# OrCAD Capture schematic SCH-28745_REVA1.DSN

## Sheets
1 TITLE PAGE: title: FRDM-KW019032; rev: A1; company: Freescale Semiconductor; note: SCH-28745 PDF: SPF-28745; note: 6501 William Cannon Drive West; note: Austin, TX 78735-8598
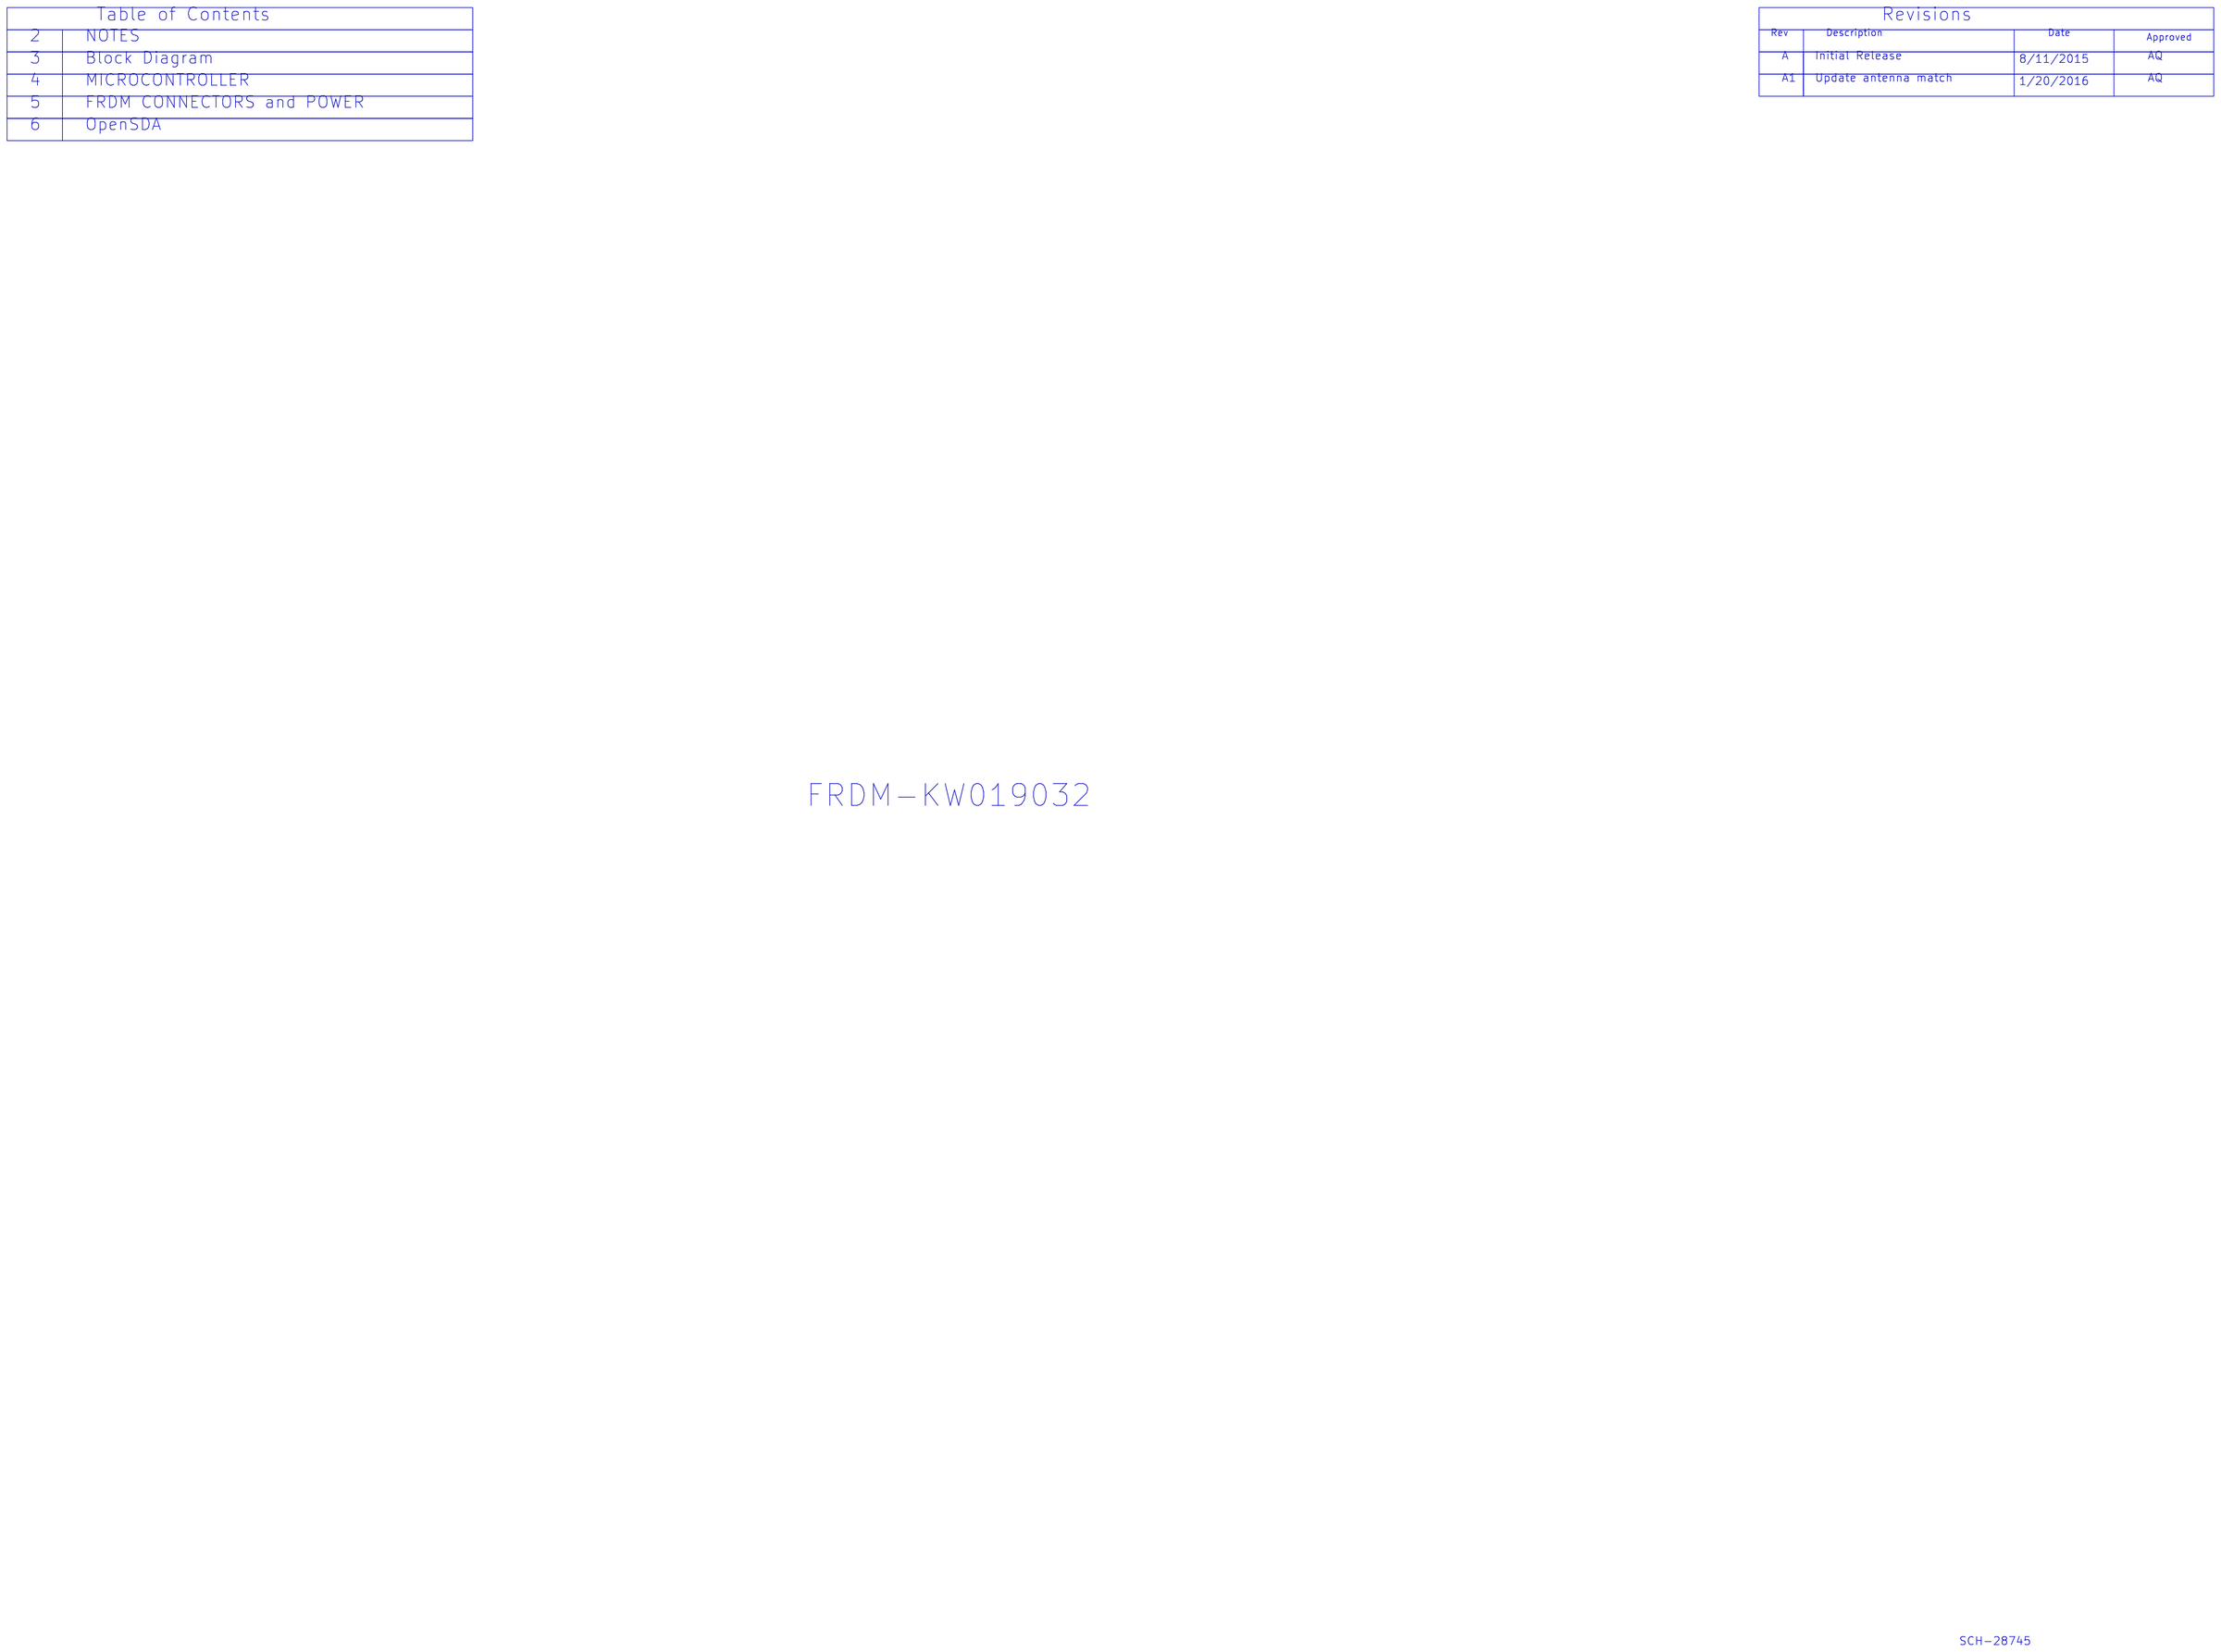
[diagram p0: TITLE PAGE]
2 NOTES
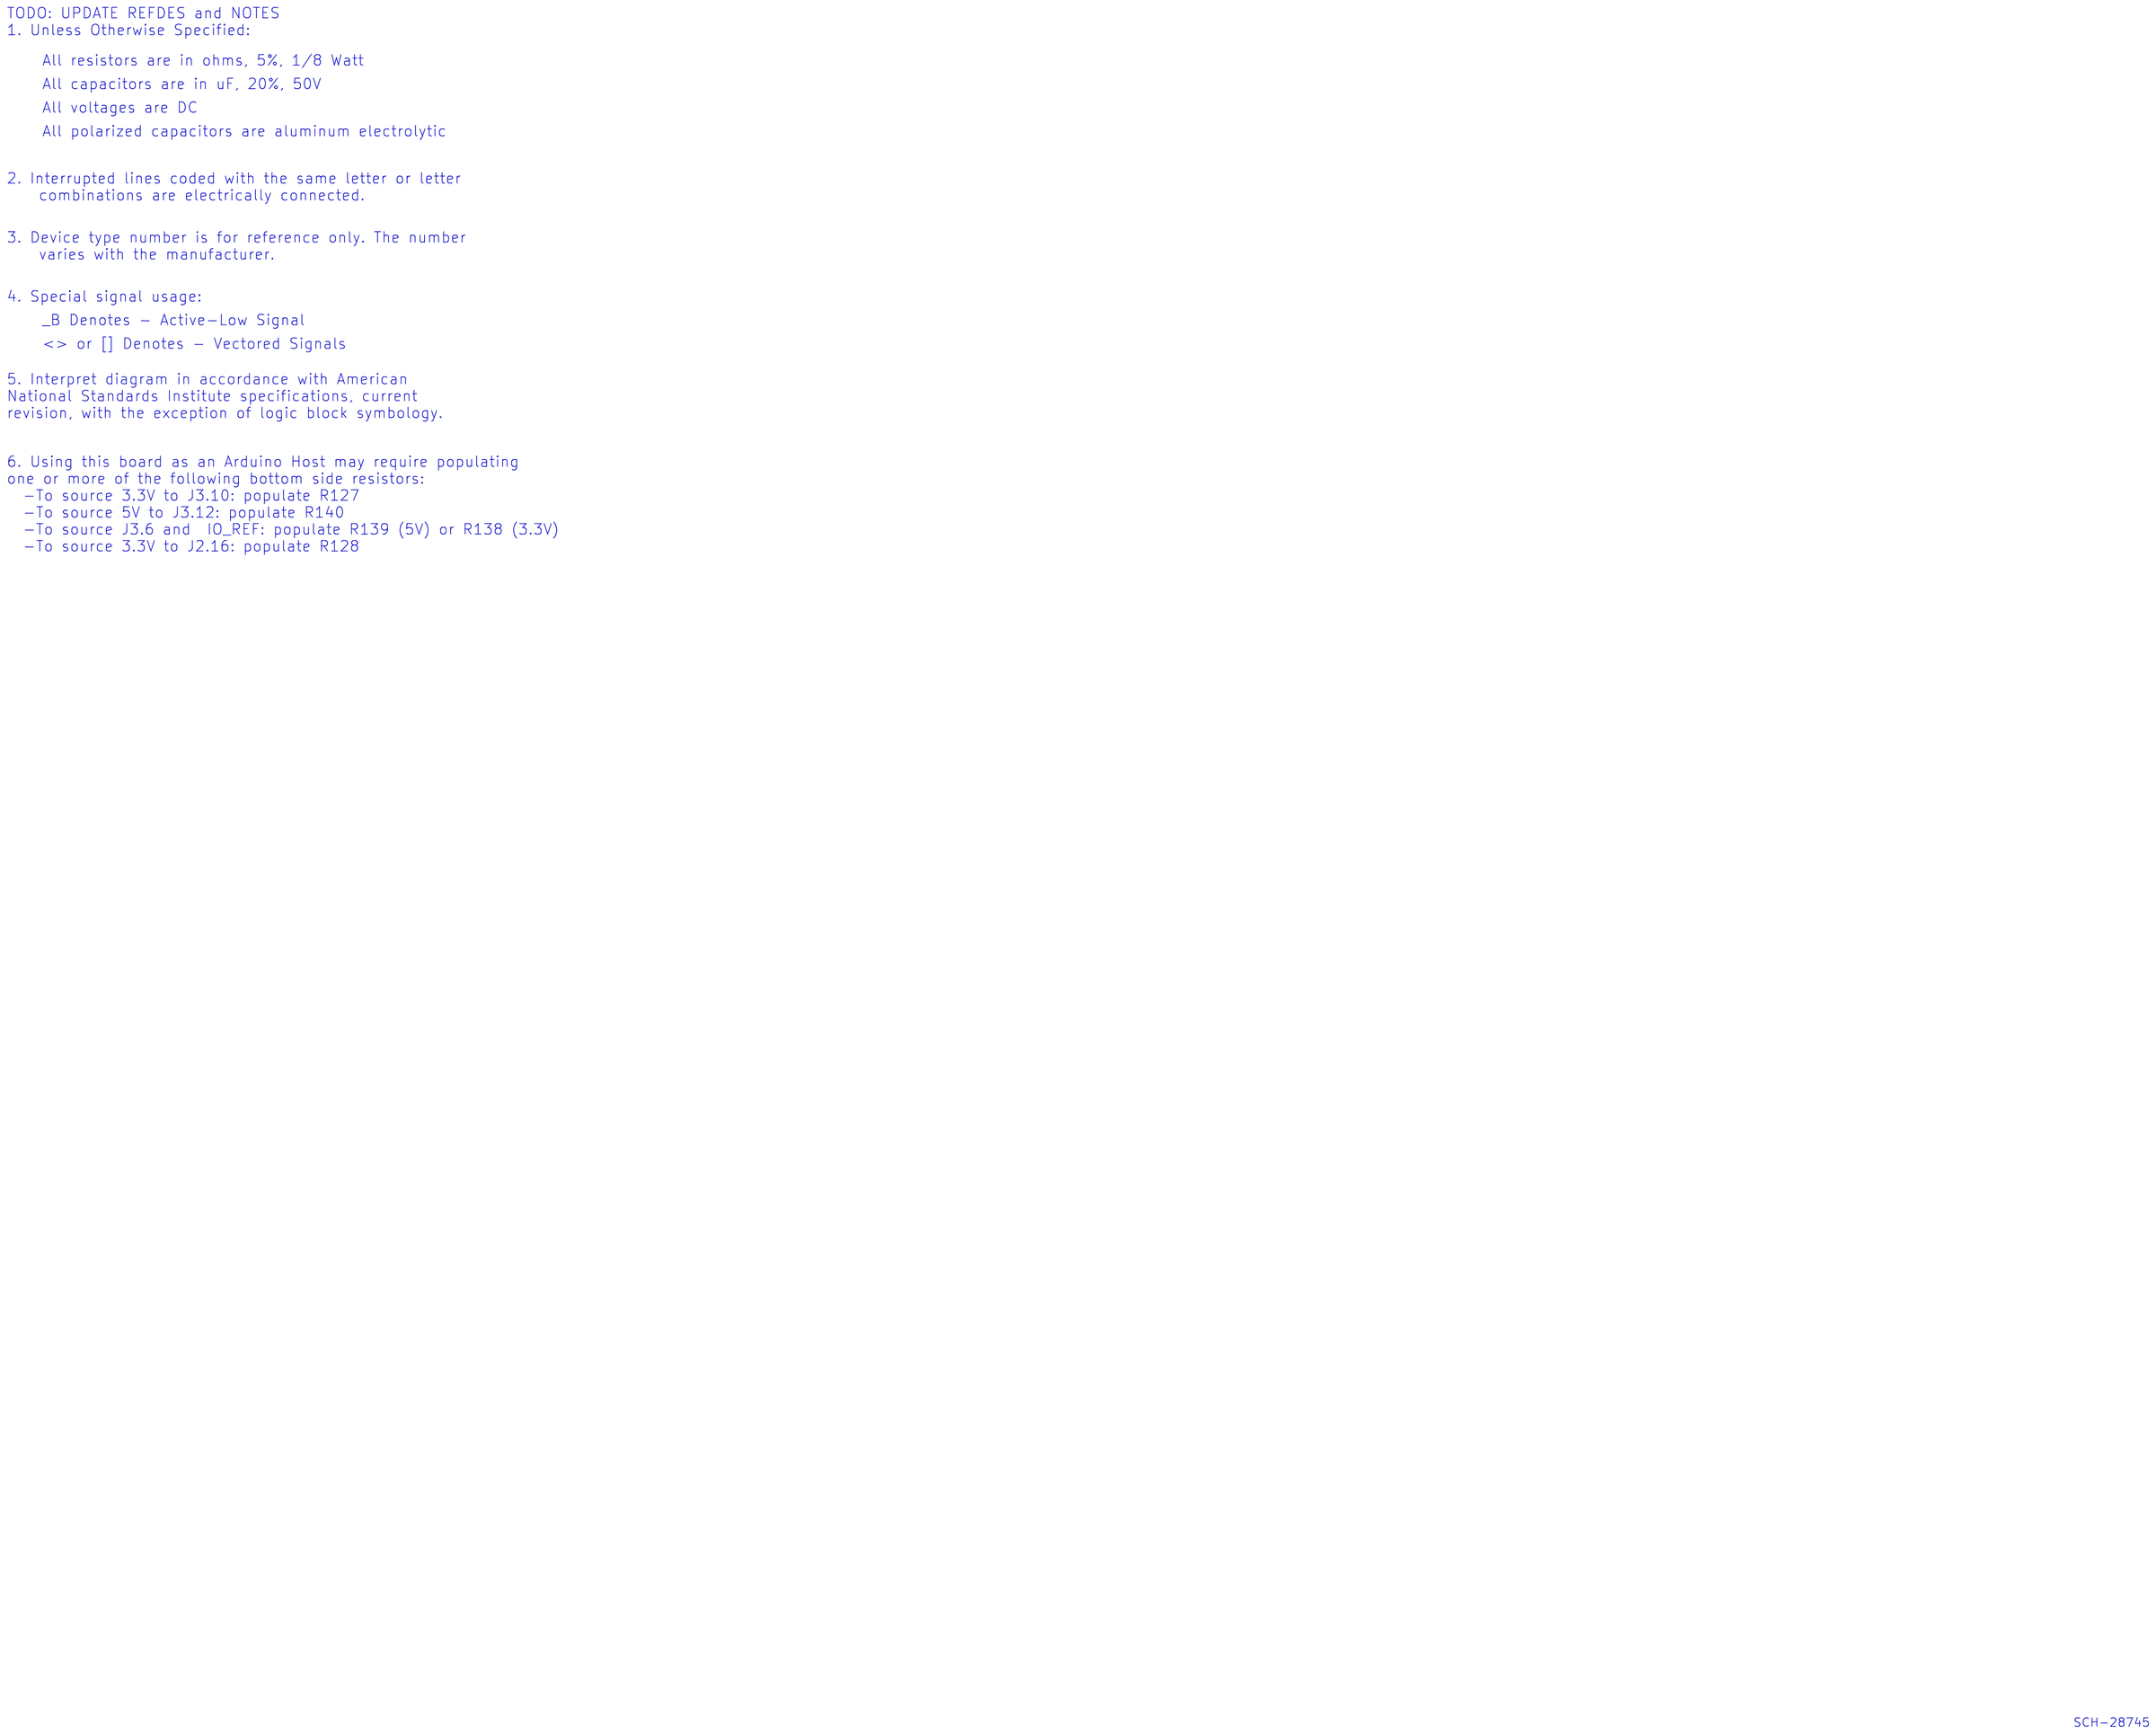
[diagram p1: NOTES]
3 BLOCK DIAGRAM
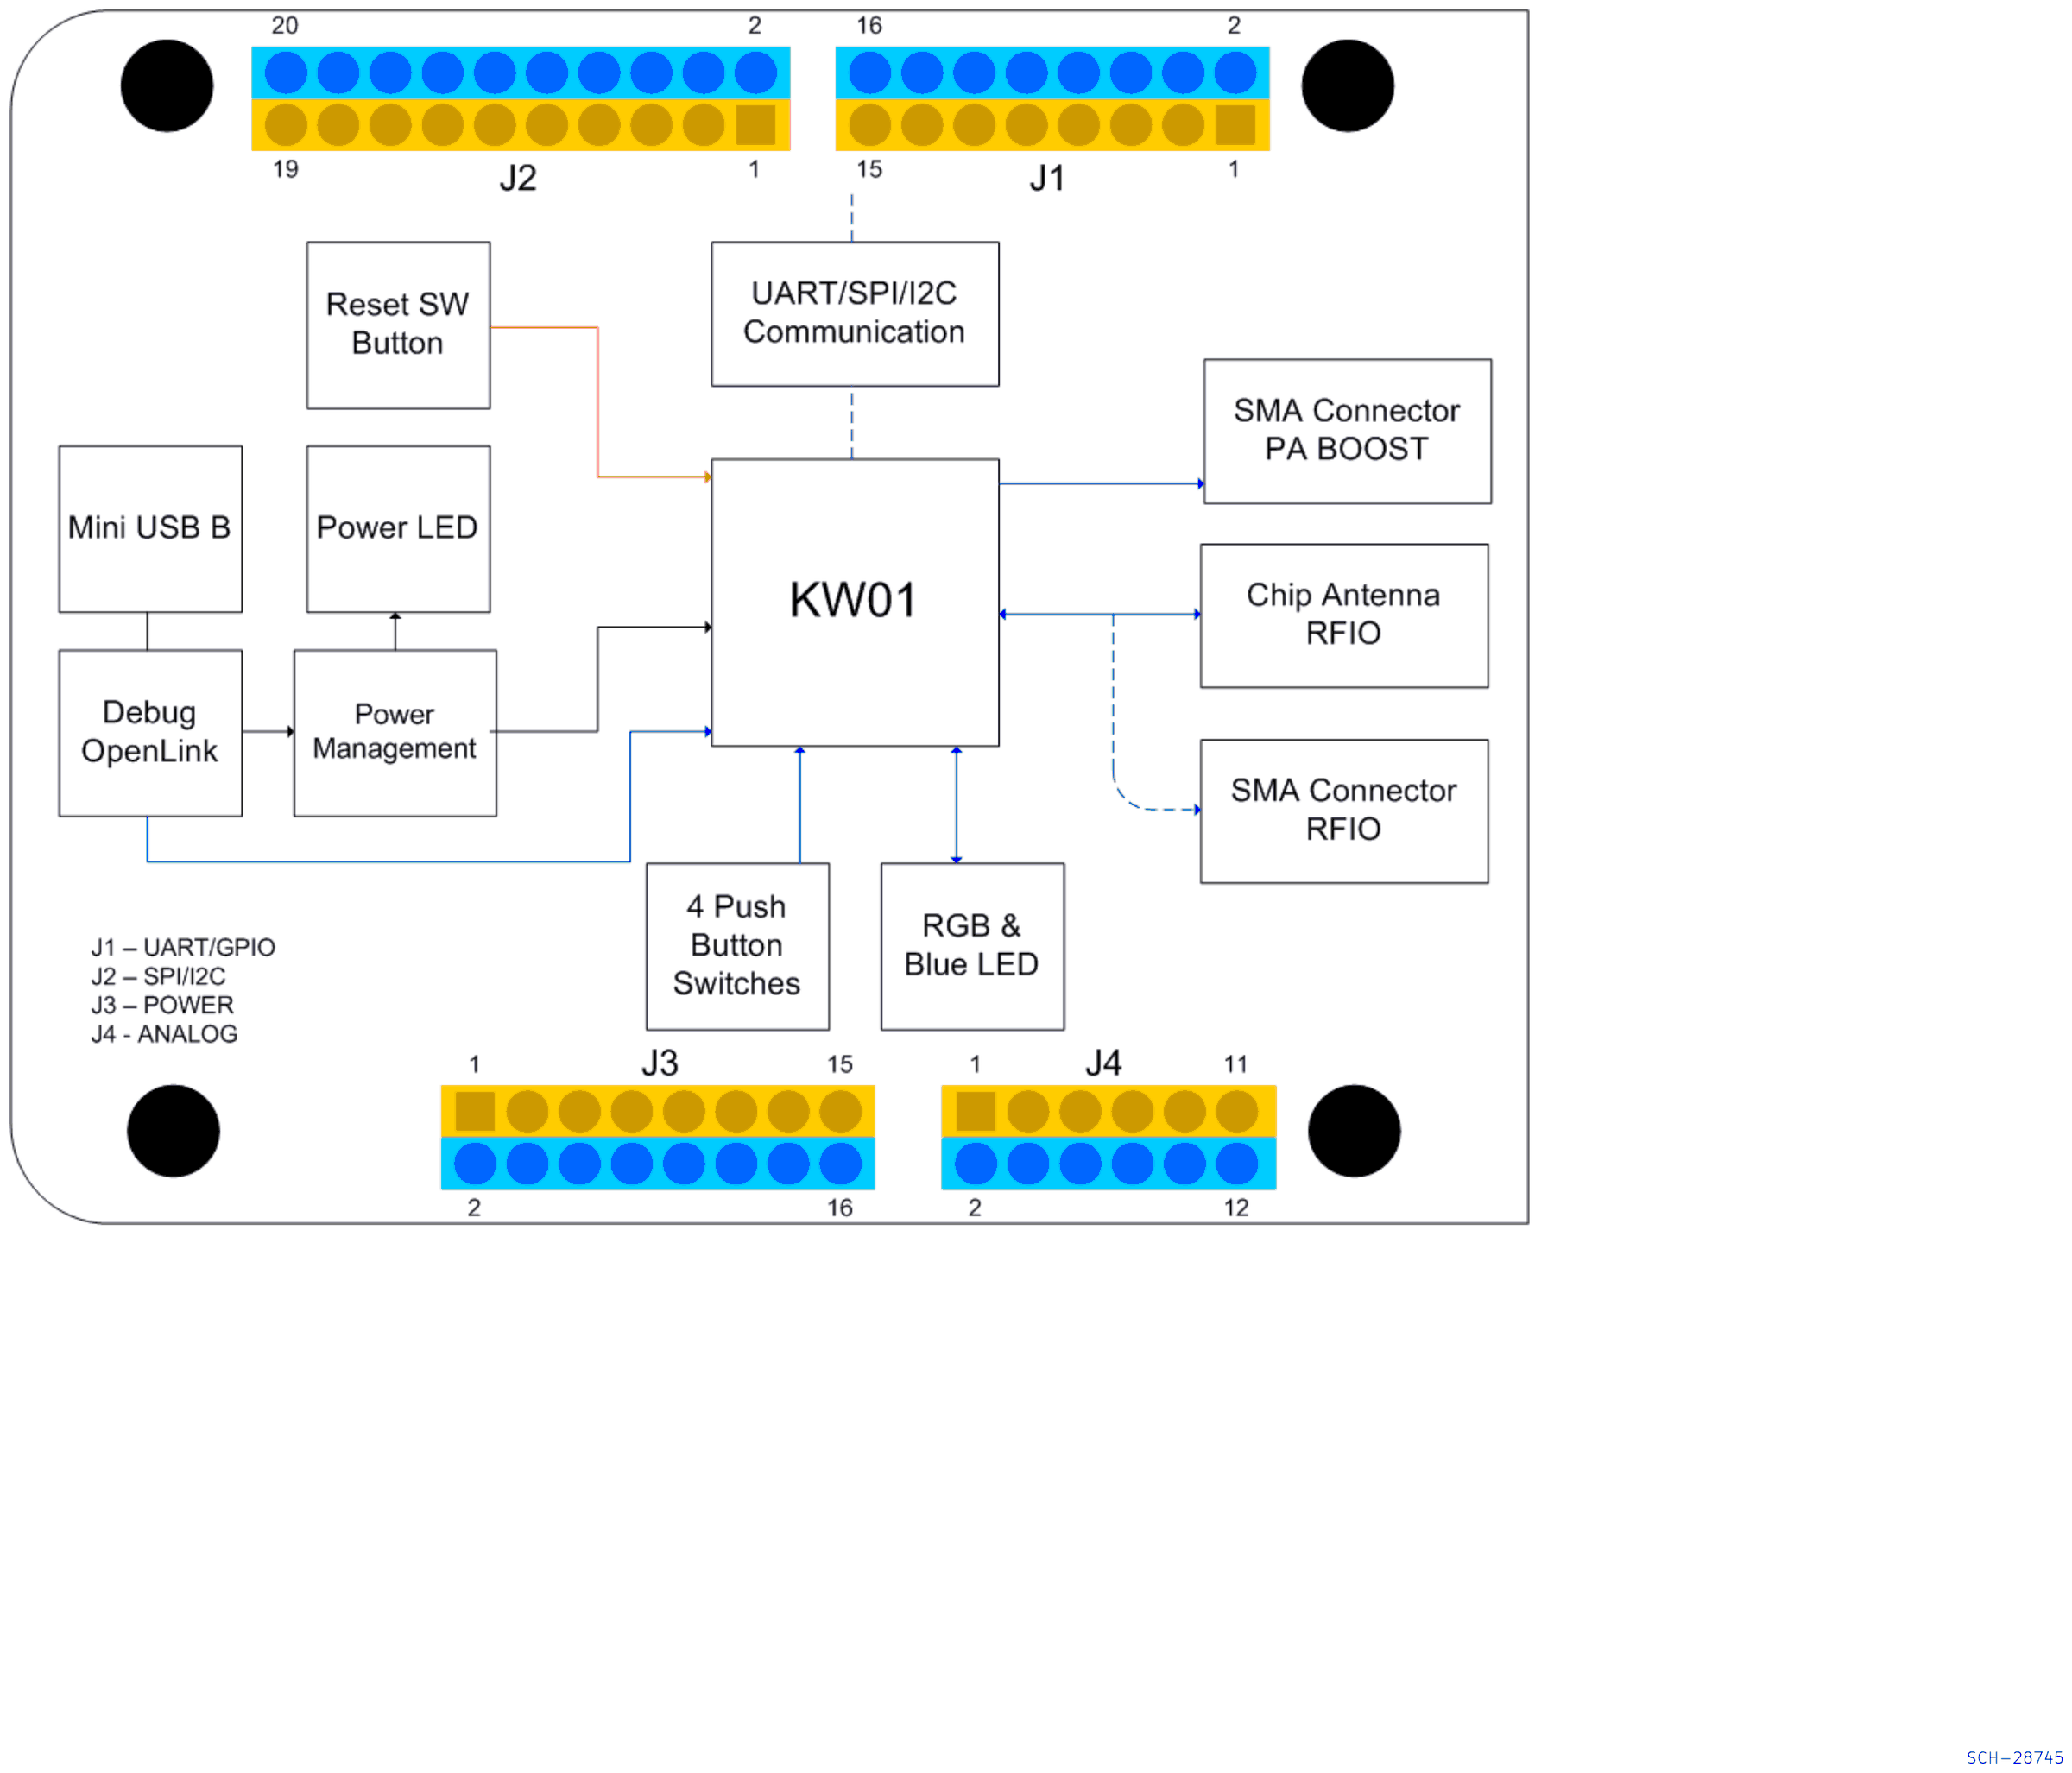
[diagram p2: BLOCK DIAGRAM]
4 MICROCONTROLLER: size C
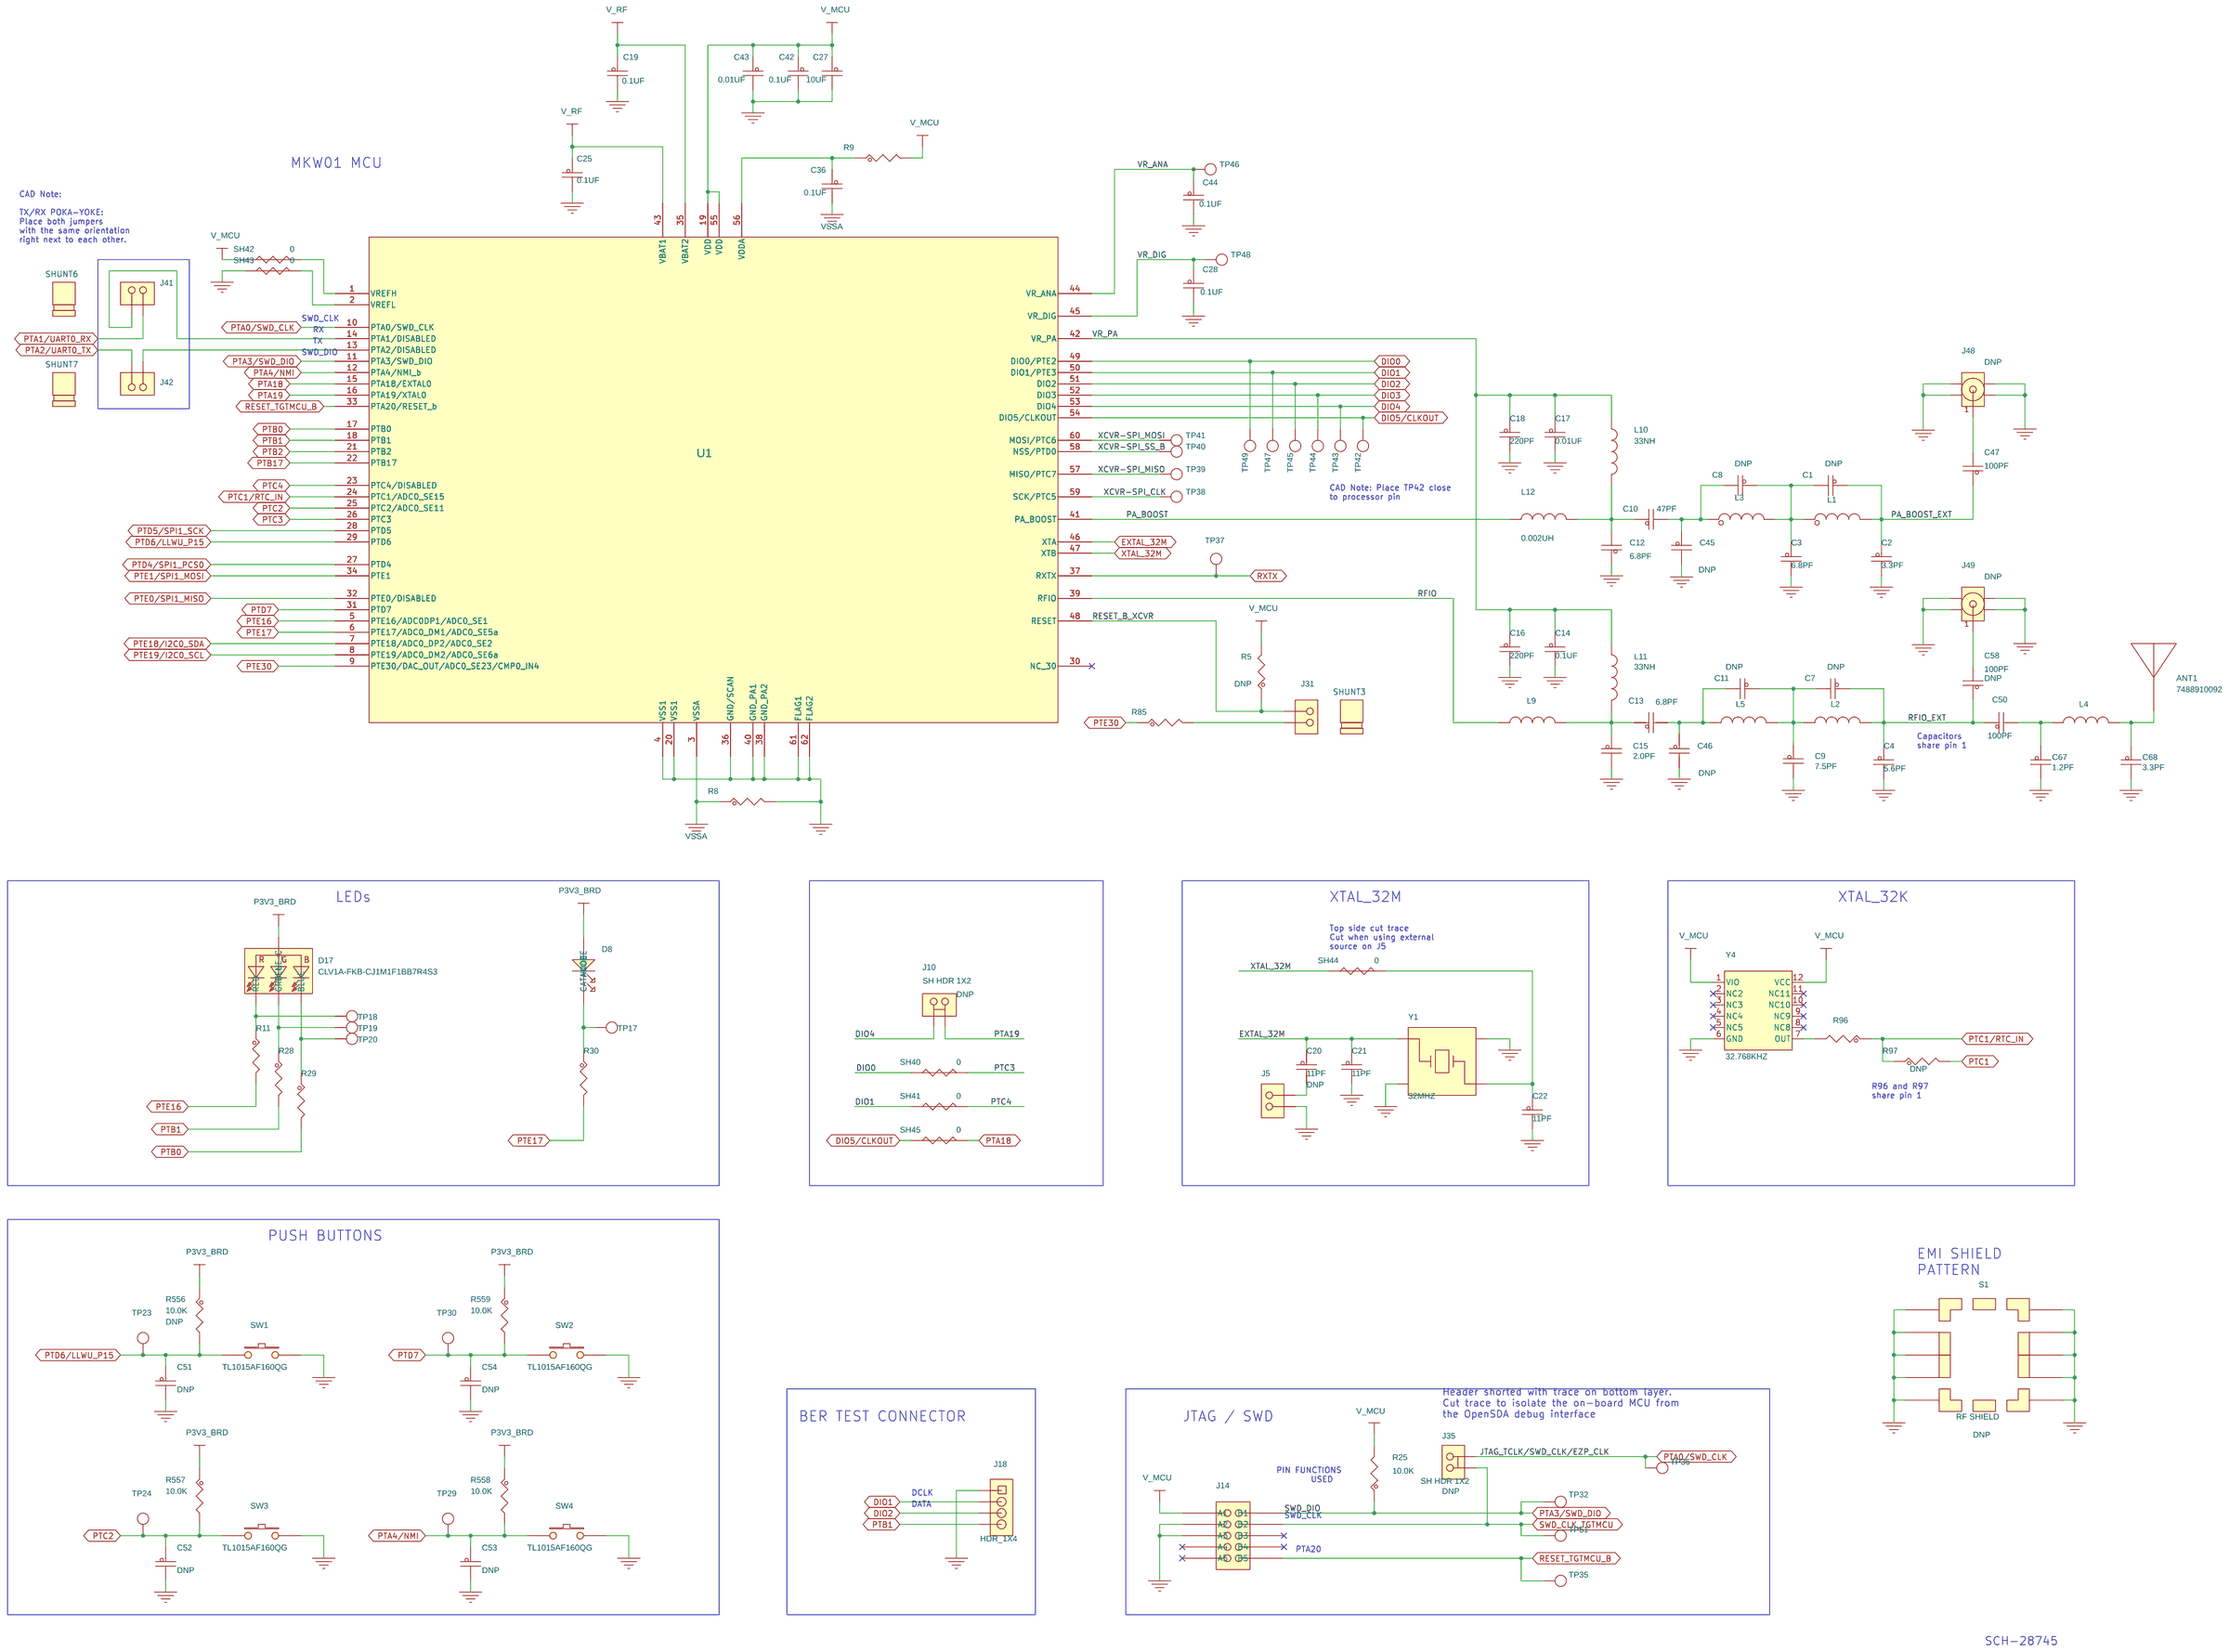
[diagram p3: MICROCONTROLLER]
5 POWER AND CONNECTORS: size C
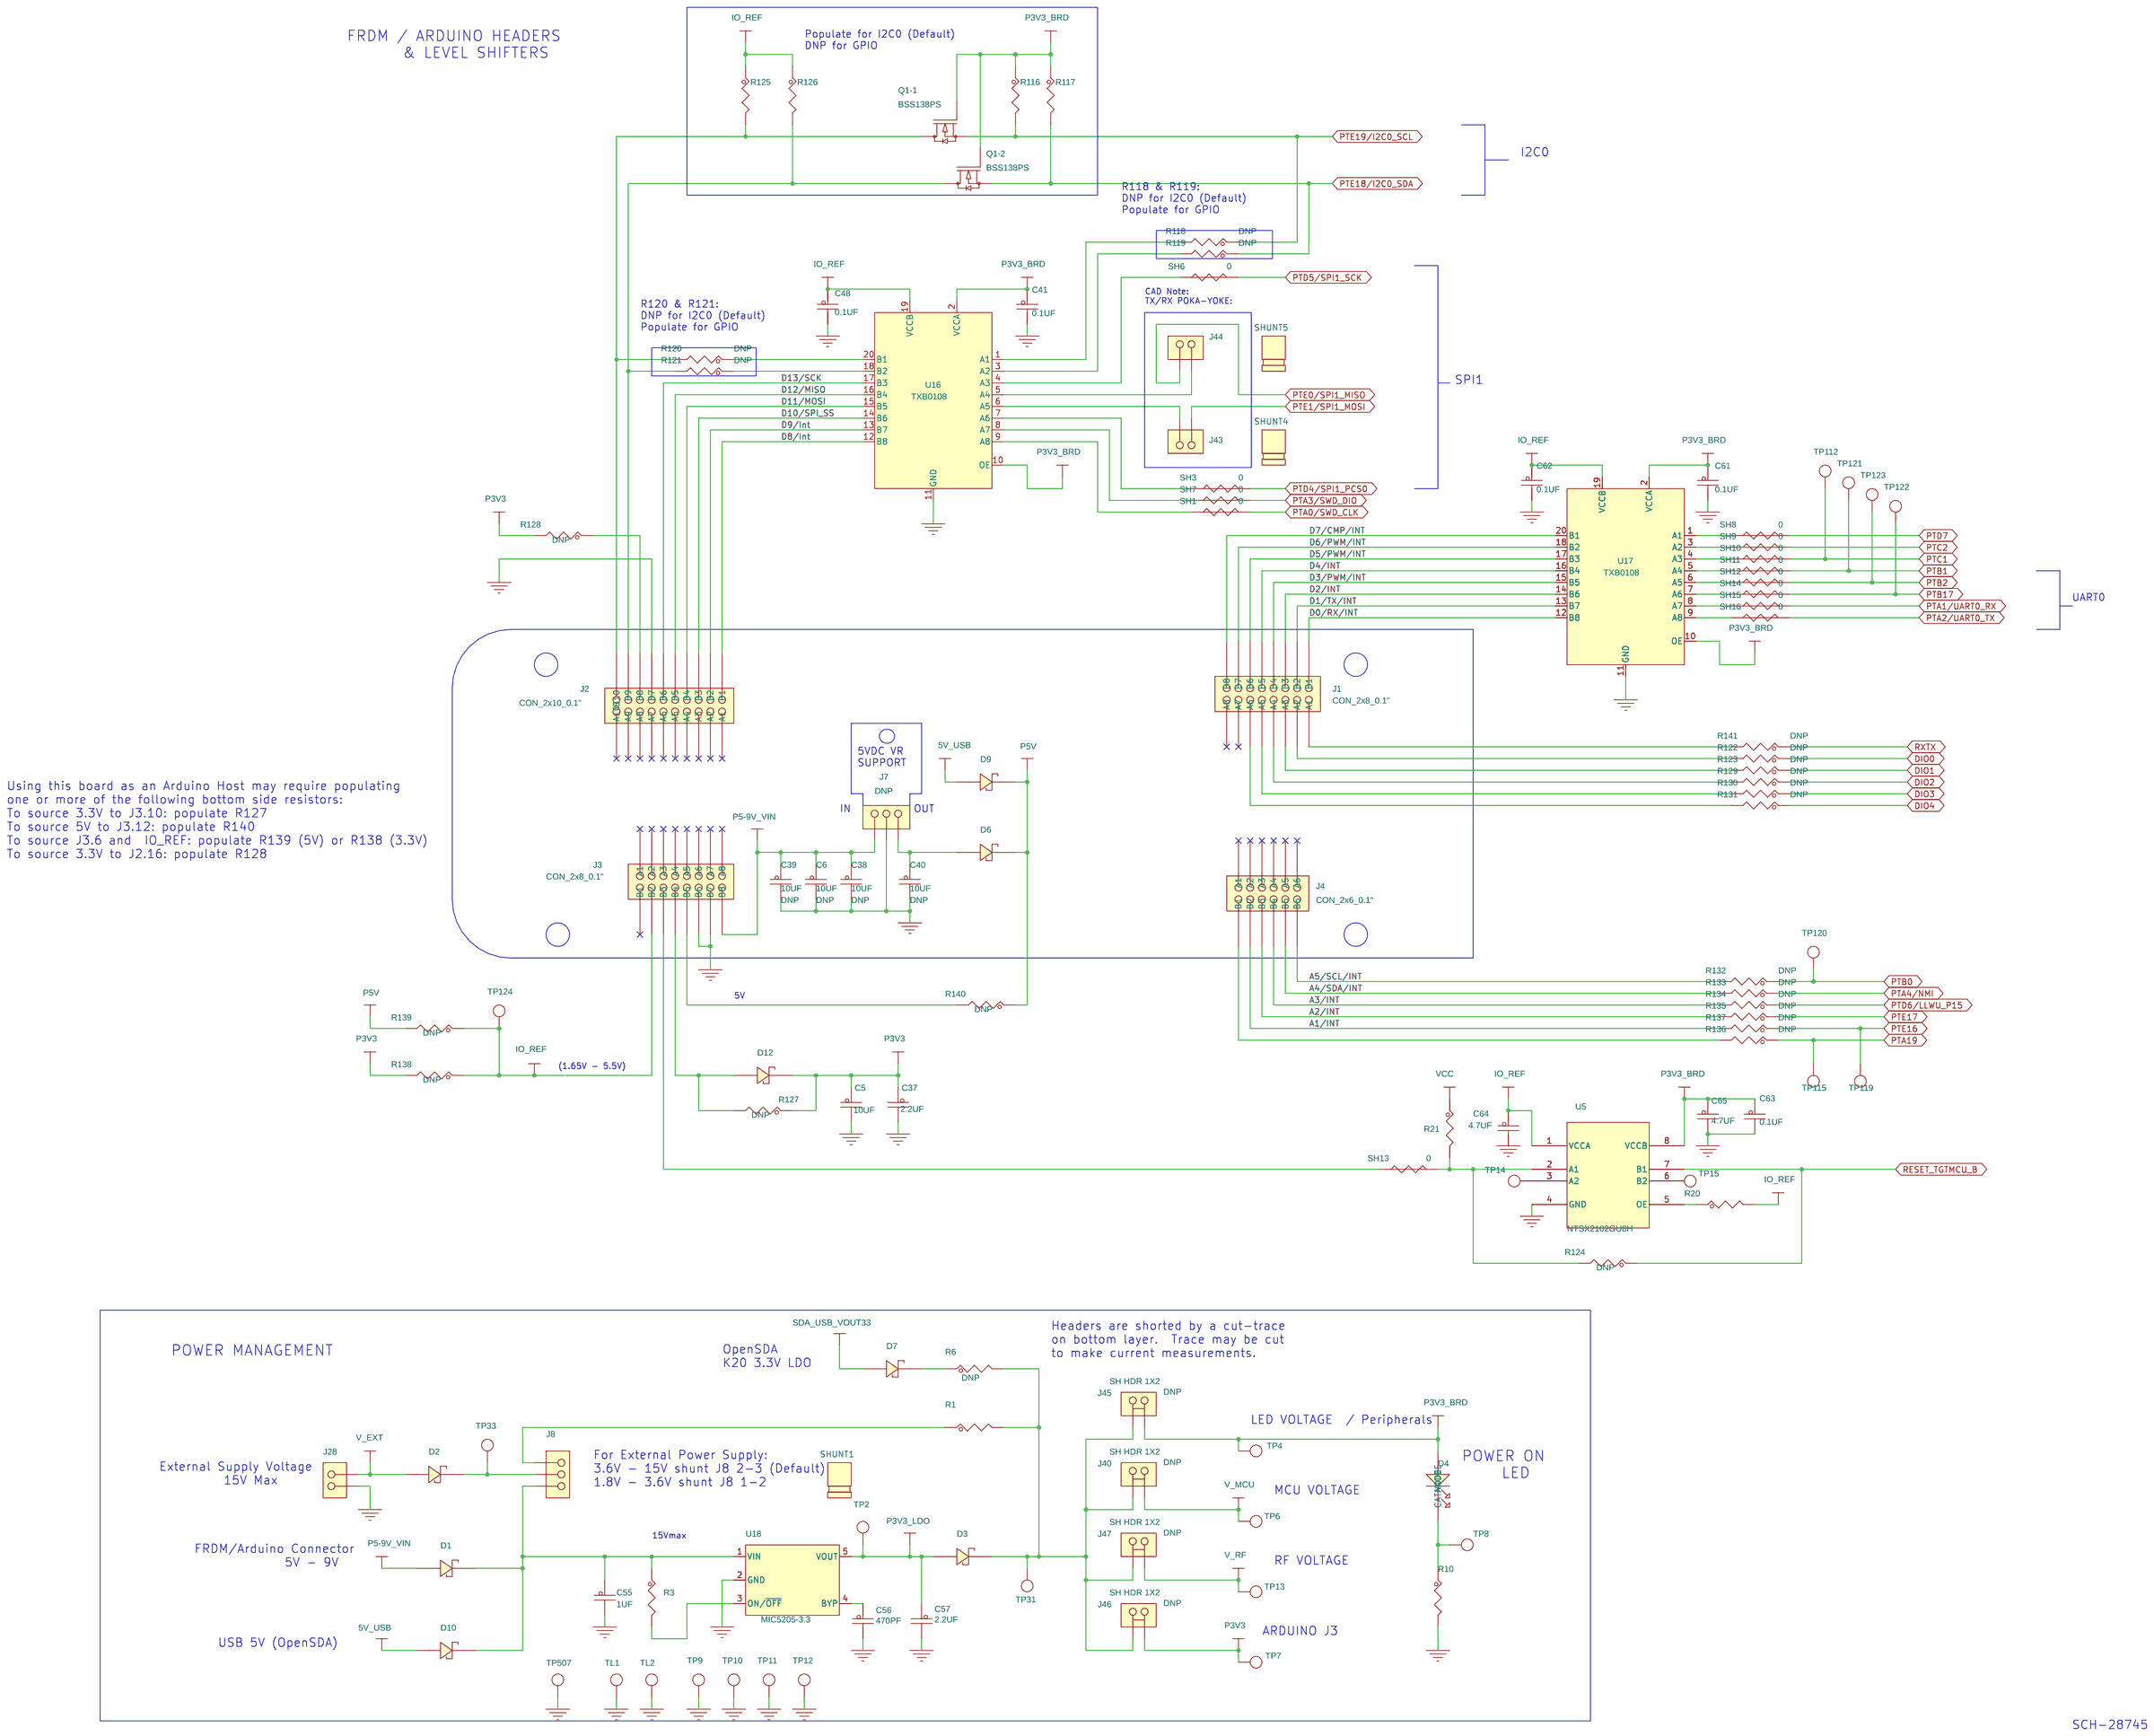
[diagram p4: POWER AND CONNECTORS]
6 OpenSDA: size C
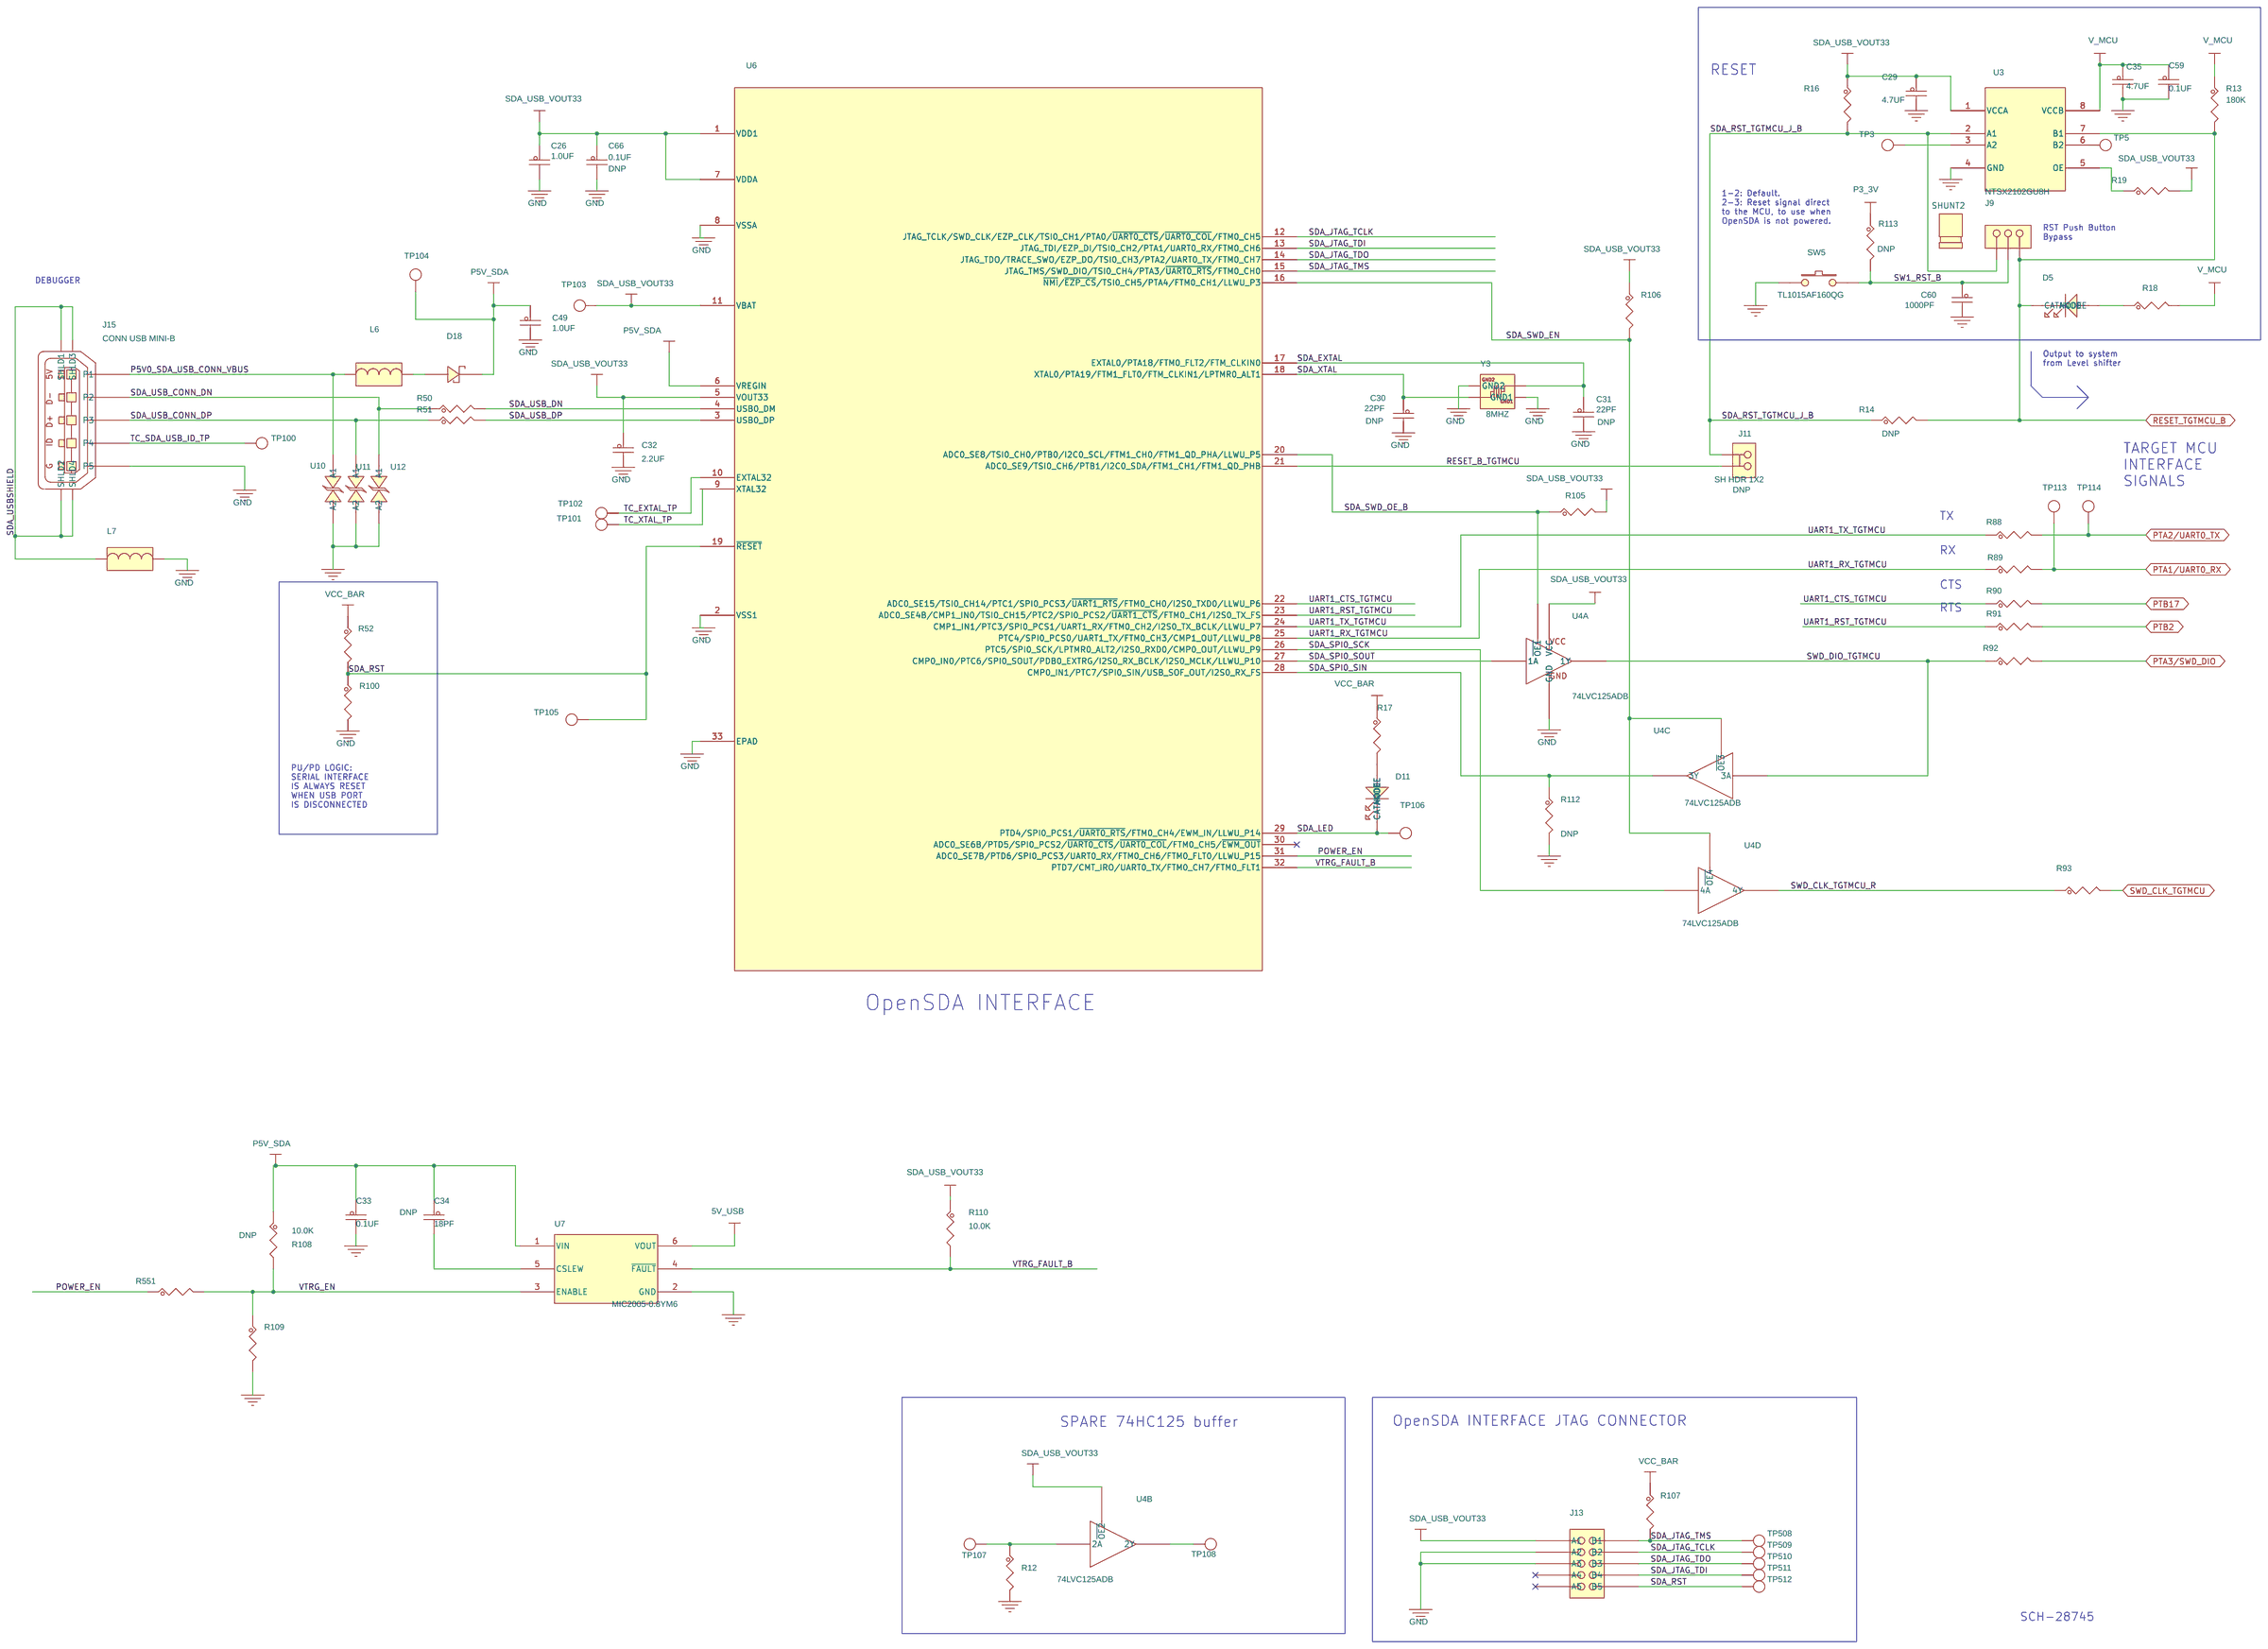
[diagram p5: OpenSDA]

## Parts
sheet MICROCONTROLLER
ANT1  7488910092  [ANT_7488910092]
C1  10PF  [0402_CC]
C2  3.3PF  [0402_CC]
C3  6.8PF  [0402_CC]
C4  5.6PF  [0402_CC]
C7  10PF  [0402_CC]
C8  10PF  [0402_CC]
C9  7.5PF  [0402_CC]
C10  47PF  [0402_CC]
C11  10PF  [0402_CC]
C12  6.8PF  [0402_CC]
C13  6.8PF  [0402_CC]
C14  0.1UF  [CC0402_25]
C15  2.0PF  [0402_CC]
C16  220PF  [0402_CC]
C17  0.01UF  [CC0402_25]
C18  220PF  [0402_CC]
C19  0.1UF  [CC0402_25]
C20  11PF  [CC0402_25]
C21  11PF  [CC0402_25]
C22  11PF  [CC0402_25]
C25  0.1UF  [CC0402_25]
C27  10UF  [CC0805_OV]
C28  0.1UF  [CC0402_25]
C36  0.1UF  [CC0402_25]
C42  0.1UF  [CC0402_25]
C43  0.01UF  [CC0402_25]
C44  0.1UF  [CC0402_25]
C45  10PF  [0402_CC]
C46  10PF  [0402_CC]
C47  100PF  [0402_CC]
C50  100PF  [0402_CC]
C51  1000PF  [CC0402_25]
C52  1000PF  [CC0402_25]
C53  1000PF  [CC0402_25]
C54  1000PF  [CC0402_25]
C58  100PF  [0402_CC]
C67  1.2PF  [0402_CC]
C68  3.3PF  [0402_CC]
D8  BLUE  [LED2_2P34_2P1X1P25]
D17  CLV1A-FKB-CJ1M1F1BB7R4S3  [LED_CREE_CLV1A_2100UM-MAXHT]
J5  HDR 1X2  [HDR102]
J10  SH HDR 1X2  [HDR102_CT]
J14  HDR 2X5  [CON_2RH_10_50]
J18  HDR_1X4  [JUMP1X4-6040]
J31  HDR 1X2  [HDR102]
J35  SH HDR 1X2  [HDR102_CT]
J41  HDR 1X2  [HDR102]
J42  HDR 1X2  [HDR102]
J48  SMA  [CON_SMA_EDGE_062]
J49  SMA  [CON_SMA_EDGE_062]
L1  5.6NH  [0402_CC]
L2  0.0068UH  [0402_CC]
L3  5.6NH  [0402_CC]
L4  15NH  [0402_CC]
L5  0.0068UH  [0402_CC]
L9  0.0047UH  [0402_CC]
L10  33NH  [0402_CC]
L11  33NH  [0402_CC]
L12  0.002UH  [0402_CC]
R5  4.7K  [RC0603_OV]
R8  0  [RC0603_OV]
R9  0  [RC0603_OV]
R11  220  [RC0402_25]
R25  10.0K  [RC0402_25]
R28  220  [RC0402_25]
R29  220  [RC0402_25]
R30  220  [RC0402_25]
R85  100  [RC0402_25]
R96  0  [RC0402_25]
R97  0  [RC0402_25]
R556  10.0K  [RC0402_25]
R557  10.0K  [RC0402_25]
R558  10.0K  [RC0402_25]
R559  10.0K  [RC0402_25]
S1  RF SHIELD  [RF_SHIELD_KW01]
SH40  0  [RC0402_25_CT]
SH41  0  [RC0402_25_CT]
SH42  0  [RC0402_25_CT]
SH43  0  [RC0402_25_CT]
SH44  0  [RC0402_25_CT]
SH45  0  [RC0402_25_CT]
SHUNT3  SHUNT  [NONE]
SHUNT6  SHUNT  [NONE]
SHUNT7  SHUNT  [NONE]
SW1  TL1015AF160QG  [SW2_2MM]
SW2  TL1015AF160QG  [SW2_2MM]
SW3  TL1015AF160QG  [SW2_2MM]
SW4  TL1015AF160QG  [SW2_2MM]
TP17  TPAD_040  [TPAD_040]
TP18  TPAD_040  [TPAD_040]
TP19  TPAD_040  [TPAD_040]
TP20  TPAD_040  [TPAD_040]
TP23  TPAD_040  [TPAD_040]
TP24  TPAD_040  [TPAD_040]
TP29  TPAD_040  [TPAD_040]
TP30  TPAD_040  [TPAD_040]
TP32  TPAD_040  [TPAD_040]
TP35  TPAD_040  [TPAD_040]
TP36  TPAD_040  [TPAD_040]
TP37  TPAD_040  [TPAD_040]
TP38  TPAD_040  [TPAD_040]
TP39  TPAD_040  [TPAD_040]
TP40  TPAD_040  [TPAD_040]
TP41  TPAD_040  [TPAD_040]
TP42  TPAD_040  [TPAD_040]
TP43  TPAD_040  [TPAD_040]
TP44  TPAD_040  [TPAD_040]
TP45  TPAD_040  [TPAD_040]
TP46  TPAD_040  [TPAD_040]
TP47  TPAD_040  [TPAD_040]
TP48  TPAD_040  [TPAD_040]
TP49  TPAD_040  [TPAD_040]
TP51  TPAD_040  [TPAD_040]
U1  MKW01Z128  [LGA60_0P5_8X8]
Y1  32MHZ  [XTLOSC4_3P2X2P5MM_SM]
Y4  32.768KHZ  [XTAL_SG-30X0LC]
sheet OpenSDA
C26  1.0UF  [CC0402_25]
C29  4.7UF  [CC0402_25]
C30  22PF  [CC0402_25]
C31  22PF  [CC0402_25]
C32  2.2UF  [CC0603_OV]
C33  0.1UF  [CC0402_25]
C34  18PF  [CC0603_OV]
C35  4.7UF  [CC0402_25]
C49  1.0UF  [CC0402_25]
C59  0.1UF  [CC0402_25]
C60  1000PF  [CC0402_25]
C66  0.1UF  [CC0402_25]
D5  RED  [LED0805]
D11  LED GREEN  [LED_0603]
D18  MSS1P3L  [SMB_2P7X1P4]
J9  HDR TH 1X3  [HDR103]
J11  SH HDR 1X2  [HDR102_CT]
J13  HDR 2X5  [CON_2RH_10_50]
J15  CONN USB MINI-B  [CON5_USB_RA_SMT]
L6  330 OHM  [IND_0805]
L7  330 OHM  [IND_0805]
R12  0  [RC0402_25]
R13  180K  [RC0402_25]
R14  0  [RC0402_25]
R16  10.0K  [RC0402_25]
R17  220  [RC0402_25]
R18  220  [RC0402_25]
R19  10.0K  [RC0402_25]
R50  33  [RC0402_25]
R51  33  [RC0402_25]
R52  4.7K  [RC0603_OV]
R88  1.0K  [RC0402_25]
R89  1.0K  [RC0402_25]
R90  1.0K  [RC0402_25]
R91  1.0K  [RC0402_25]
R92  1.0K  [RC0402_25]
R93  1.0K  [RC0402_25]
R100  10K  [RC0603_OV]
R105  10K  [RC0603_OV]
R106  27K  [RC0402_25]
R107  10K  [RC0603_OV]
R108  10.0K  [RC0402_25]
R109  15K  [RC0402_25]
R110  10.0K  [RC0402_25]
R112  27K  [RC0402_25]
R113  15K  [RC0402_25]
R551  1.0K  [RC0402_25]
SHUNT2  SHUNT  [NONE]
SW5  TL1015AF160QG  [SW2_2MM]
TP3  TPAD_030  [TPAD_030]
TP5  TPAD_030  [TPAD_030]
TP100  TPAD_030  [TPAD_030]
TP101  TPAD_030  [TPAD_030]
TP102  TPAD_030  [TPAD_030]
TP103  TPAD_030  [TPAD_030]
TP104  TPAD_040  [TPAD_040]
TP105  TPAD_030  [TPAD_030]
TP106  TPAD_030  [TPAD_030]
TP107  TPAD_030  [TPAD_030]
TP108  TPAD_030  [TPAD_030]
TP113  TPAD_040  [TPAD_040]
TP114  TPAD_040  [TPAD_040]
TP508  TPAD_030  [TPAD_030]
TP509  TPAD_030  [TPAD_030]
TP510  TPAD_030  [TPAD_030]
TP511  TPAD_030  [TPAD_030]
TP512  TPAD_030  [TPAD_030]
U3  NTSX2102GU8H  [XQFN8_1P45X1P25MM]
U4  74LVC125ADB  [SSOP14]  (sections A,B,C,D)
U6  MK20DX128VFM5  [QFN32_S142EP]
U7  MIC2005-0.8YM6  [SOT23-6_A]
U10  0402ESDA-MLP  [0402_MLP]
U11  0402ESDA-MLP  [0402_MLP]
U12  0402ESDA-MLP  [0402_MLP]
Y3  8MHZ  [XTLOSC4_5X3MM_SM]
sheet POWER AND CONNECTORS
C5  10UF  [CC0805_OV]
C6  10UF  [CC0805_OV]
C37  2.2UF  [CC0603_OV]
C38  10UF  [CC0805_OV]
C39  10UF  [CC0805_OV]
C40  10UF  [CC0805_OV]
C41  0.1UF  [CC0402_25]
C48  0.1UF  [CC0402_25]
C55  1UF  [CC0805_OV]
C56  470PF  [CC0402_25]
C57  2.2UF  [CC0603_OV]
C61  0.1UF  [CC0402_25]
C62  0.1UF  [CC0402_25]
C63  0.1UF  [CC0402_25]
C64  4.7UF  [CC0402_25]
C65  4.7UF  [CC0402_25]
D1  MSS1P3L  [SMB_2P7X1P4]
D2  MSS1P3L  [SMB_2P7X1P4]
D3  MSS1P3L  [SMB_2P7X1P4]
D4  RED  [LED0805]
D6  MSS1P3L  [SMB_2P7X1P4]
D7  MSS1P3L  [SMB_2P7X1P4]
D9  MSS1P3L  [SMB_2P7X1P4]
D10  MSS1P3L  [SMB_2P7X1P4]
D12  MSS1P3L  [SMB_2P7X1P4]
J1  CON_2x8_0.1"  [MTCONN_JT254F-D180-850-208-10D]
J2  CON_2x10_0.1"  [MTCONN_JT254F-D180-850-210-10D]
J3  CON_2x8_0.1"  [MTCONN_JT254F-D180-850-208-10D]
J4  CON_2x6_0.1"  [MTCONN_JT254F-D180-850-206-10D]
J7  HDR TH 1X3  [HDR103]
J8  HDR TH 1X3  [HDR103]
J28  HDR 1X2  [HDR102]
J40  SH HDR 1X2  [HDR102_CT]
J43  HDR 1X2  [HDR102]
J44  HDR 1X2  [HDR102]
J45  SH HDR 1X2  [HDR102_CT]
J46  SH HDR 1X2  [HDR102_CT]
J47  SH HDR 1X2  [HDR102_CT]
Q1  BSS138PS  [BSS138_DUAL_SC88]  (sections -1,-2)
R1  0  [RC0603_OV]
R3  0  [RC0402_25]
R6  0  [RC0603_OV]
R10  220  [RC0402_25]
R20  10.0K  [RC0402_25]
R21  10.0K  [RC0402_25]
R116  4.7K  [RC0603_OV]
R117  4.7K  [RC0603_OV]
R118  0  [RC0402_25]
R119  0  [RC0402_25]
R120  0  [RC0402_25]
R121  0  [RC0402_25]
R122  0  [RC0402_25]
R123  0  [RC0402_25]
R124  0  [RC0402_25]
R125  4.7K  [RC0603_OV]
R126  4.7K  [RC0603_OV]
R127  0  [RC0402_25]
R128  0  [RC0402_25]
R129  0  [RC0402_25]
R130  0  [RC0402_25]
R131  0  [RC0402_25]
R132  0  [RC0402_25]
R133  0  [RC0402_25]
R134  0  [RC0402_25]
R135  0  [RC0402_25]
R136  0  [RC0402_25]
R137  0  [RC0402_25]
R138  0  [RC0402_25]
R139  0  [RC0402_25]
R140  0  [RC0402_25]
R141  0  [RC0402_25]
SH1  0  [RC0402_25_CT]
SH3  0  [RC0402_25_CT]
SH6  0  [RC0402_25_CT]
SH7  0  [RC0402_25_CT]
SH8  0  [RC0402_25_CT]
SH9  0  [RC0402_25_CT]
SH10  0  [RC0402_25_CT]
SH11  0  [RC0402_25_CT]
SH12  0  [RC0402_25_CT]
SH13  0  [RC0402_25_CT]
SH14  0  [RC0402_25_CT]
SH15  0  [RC0402_25_CT]
SH16  0  [RC0402_25_CT]
SHUNT1  SHUNT  [NONE]
SHUNT4  SHUNT  [NONE]
SHUNT5  SHUNT  [NONE]
TL1  TESTLOOP  [TESTPOINT_135_070MIL]
TL2  TESTLOOP  [TESTPOINT_135_070MIL]
TP2  TPAD_040  [TPAD_040]
TP4  TPAD_040  [TPAD_040]
TP6  TPAD_040  [TPAD_040]
TP7  TPAD_040  [TPAD_040]
TP8  TPAD_040  [TPAD_040]
TP9  TPAD_040  [TPAD_040]
TP10  TPAD_040  [TPAD_040]
TP11  TPAD_040  [TPAD_040]
TP12  TPAD_040  [TPAD_040]
TP13  TPAD_040  [TPAD_040]
TP14  TPAD_030  [TPAD_030]
TP15  TPAD_030  [TPAD_030]
TP31  TPAD_040  [TPAD_040]
TP33  TPAD_040  [TPAD_040]
TP112  TPAD_040  [TPAD_040]
TP115  TPAD_040  [TPAD_040]
TP119  TPAD_040  [TPAD_040]
TP120  TPAD_040  [TPAD_040]
TP121  TPAD_040  [TPAD_040]
TP122  TPAD_040  [TPAD_040]
TP123  TPAD_040  [TPAD_040]
TP124  TPAD_040  [TPAD_040]
TP507  TESTLOOP_BLACK  [TP_TH_063]
U5  NTSX2102GU8H  [XQFN8_1P45X1P25MM]
U16  TXB0108  [TI_PW_TSSOP20]
U17  TXB0108  [TI_PW_TSSOP20]
U18  MIC5205-3.3  [SOT23-5]

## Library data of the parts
ANT1 = ANT_Wurth_7488910092
C1 C7 C8 C11 C45 C46 = CAP_NP: CAP CER 10PF 50V 5% C0G 0402; AGILE_PN: 150-75265; ASSY_OPT: DNP; CAD_APPROVED: YES; FPLIST: CC0402_25,CC0402_HD,0402_CC; HEIGHT: 0.635MM; MFG_NAME01: AVX; MFG_PN01: 04025A100JAT2A; ROHS: Yes; TOL: 5%; Tolerance: 5%; VOLTAGE: 50V
C2 C68 = CAP_NP: CAP CER 3.3PF 25V 0.1PF -- 0402; AGILE_PN: 150-78484; CAD_APPROVED: Yes; FPLIST: CC0402_25,CC0402_HD,0402_CC; HEIGHT: 0.5MM; MFG_NAME01: AVX; MFG_PN01: 04023J3R3BBSTR; ROHS: Yes; VOLTAGE: 25V
C3 C12 C13 = CAP_NP: CAP CER 6.8PF 50V 0.5PF C0G 0402; AGILE_PN: 150-30300; CAD_APPROVED: Yes; FPLIST: CC0402_25,CC0402_HD,0402_CC; HEIGHT: 0.55MM; MFG_NAME01: MURATA; MFG_PN01: GRM1555C1H6R8DZ01J; ROHS: Yes; Tolerance: 0.5PF %; VOLTAGE: 50V
C4 = CAP_NP: CAP CER 5.6PF 50V +/-0.25PF C0G CC0402; AGILE_PN: 150-75521; CAD_APPROVED: Yes; FPLIST: CC0402_25,CC0402_HD,0402_CC; HEIGHT: 0.55MM; MFG_NAME01: MURATA; MFG_PN01: GJM1555C1H5R6CB01D; ROHS: Yes; Tolerance: 0.25PF; VOLTAGE: 16V
C9 = CAP_NP: CAP CER 7.5PF 50V 0.5PF C0G 0402; AGILE_PN: 150-79179; CAD_APPROVED: Yes; FPLIST: CC0402_25,CC0402_HD,0402_CC; HEIGHT: 0.55MM; MFG_NAME01: MURATA; MFG_PN01: GRM1555C1H7R5DA01D; ROHS: Yes; Tolerance: 0.5PF
C10 = CAP_NP: CAP CER 47PF 50V 5% C0G 0402; FPLIST: CC0402_25,CC0402_HD,0402_CC; HEIGHT: 0.64 MM; MFG_NAME01: MURATA; MFG_PN01: GRM1555C1H470JA01D; ROHS: Yes; Tolerance: 5%; VOLTAGE: 50V
C14 C19 C25 C28 C33 C36 C41 C42 C44 C48 C59 C61-C63 = CAP_NP: CAP CER 0.1UF 16V 10% X7R 0402; AGILE_PN: 150-75182; CAD_APPROVED: Yes; FPLIST: CC0402_25,CC0402_HD,0402_CC; HEIGHT: 0.635MM; MFG_NAME01: KEMET; MFG_PN01: C0402C104K4RAC; ROHS: Yes; Tolerance: 10%; VOLTAGE: 16V
C15 = CAP_NP: CAP CER 2PF 50V 0.25PF C0G 0402; AGILE_PN: 150-77501; CAD_APPROVED: Yes; FPLIST: CC0402_25,CC0402_HD,0402_CC; HEIGHT: 0.55 MM; MFG_NAME01: MURATA; MFG_PN01: GRM1555C1H2R0CA01B; ROHS: Yes; Tolerance: 0.25PF; VOLTAGE: 50V
C16 C18 = CAP_NP: CAP CER 220PF 50V 5% C0G 0402; AGILE_PN: 150-30297; CAD_APPROVED: Yes; FPLIST: CC0402_25,CC0402_HD,0402_CC; HEIGHT: 0.55MM; MFG_NAME01: KEMET; MFG_PN01: C0402C221J5GAC; ROHS: Yes; Tolerance: 5%; VOLTAGE: 50V
C17 C43 = CAP_NP: CAP CER 0.01UF 50V 10% X7R 0402; CAD_APPROVED: Yes; FPLIST: CC0402_25,CC0402_HD,0402_CC; HEIGHT: 0.55 MM; MFG_NAME01: KEMET; MFG_PN01: C0402C103K5RAC; ROHS: Yes; Tolerance: 10%; VOLTAGE: 50V
C20 = CAP_NP: CAP CER 11PF 50V 1% C0G 0402; ASSY_OPT: DNP; CAD_APPROVED: Yes; FPLIST: CC0402_25,CC0402_HD,0402_CC; HEIGHT: 0.55MM; MFG_NAME01: KEMET; MFG_PN01: CBR04C110F5GAC; ROHS: Yes; Tolerance: 5%; VOLTAGE: 50V
C21 C22 = CAP_NP: CAP CER 11PF 50V 1% C0G 0402; CAD_APPROVED: Yes; FPLIST: CC0402_25,CC0402_HD,0402_CC; HEIGHT: 0.55MM; MFG_NAME01: KEMET; MFG_PN01: CBR04C110F5GAC; ROHS: Yes; Tolerance: 5%; VOLTAGE: 50V
C5 C27 = CAP_NP: CAP CER 10UF 10V 10% X7R 0805; CAD_APPROVED: Yes; FPLIST: CC0805_OV,CC0805,0805_CC; HEIGHT: 1.4MM; MFG_NAME01: MURATA; MFG_PN01: GRM21BR71A106KE51L; ROHS: Yes; Tolerance: 10%; VOLTAGE: 10V
C47 C50 = CAP_NP: CAP CER 100PF 50V 5% C0G 0402; AGILE_PN: 150-30247; CAD_APPROVED: Yes; FPLIST: CC0402_25,CC0402_HD,0402_CC; HEIGHT: 0.55MM; MFG_NAME01: KEMET; MFG_PN01: C0402C101J5GAC; ROHS: Yes; Tolerance: 5%; VOLTAGE: 50V
C51-C54 = CAP_NP: CAP CER 1000PF 50V 5% C0G 0402; AGILE_PN: 150-76334; ASSY_OPT: DNP; CAD_APPROVED: Yes; FPLIST: CC0402_25,CC0402_HD,0402_CC; HEIGHT: 0.55MM; MFG_NAME01: MURATA; MFG_PN01: GRM1555C1H102JA01D; ROHS: Yes; Tolerance: 5%; VOLTAGE: 50V
C58 = CAP_NP: CAP CER 100PF 50V 5% C0G 0402; AGILE_PN: 150-30247; ASSY_OPT: DNP; CAD_APPROVED: Yes; FPLIST: CC0402_25,CC0402_HD,0402_CC; HEIGHT: 0.55MM; MFG_NAME01: KEMET; MFG_PN01: C0402C101J5GAC; ROHS: Yes; Tolerance: 5%; VOLTAGE: 50V
C67 = CAP_NP: CAP CER 1.2PF 50V 0.1PF C0G 0402; FPLIST: CC0402_25,CC0402_HD,0402_CC; HEIGHT: 0.5MM; MFG_NAME01: JOHANSON; MFG_PN01: 500R07S1R2BV4T; ROHS: Yes; VOLTAGE: 50V
D8 = LED: LED BLUE SGL 20MA SMT 0805; AGILE_PN: 370-76451; CAD_APPROVED: Yes; HEIGHT: 0.9MM; MFG_NAME01: LITE ON; MFG_PN01: LTST-C171TBKT; ROHS: Yes
D17 = LED_RGB_CREE: LED - RGB, CLV1A-FKB-CJ1M1F1BB7R4S3, 675/527/470MCD(TYP.), SMD
J5 J28 J31 J41-J44 = CONN_HDR_2X1: HDR 1X2 TH 100MIL SP 330H SN 115L; AGILE_PN: 210-76752; CAD_APPROVED: Yes; HEIGHT: 8.58MM; MFG_NAME01: SAMTEC; MFG_PN01: TSW-102-23-T-S; ROHS: Yes
J10 J11 J35 J40 J45-J47 = CONN_HDR_2X1_CT: ASSY_OPT: DNP
J13 J14 = CONN_HDR_5X2: CONN,HEAD,2X5,STR,50/50 CON-2RH-10-50; AGILE_PN: 210-07961-00; CAD_APPROVED: Yes; HEIGHT: 3.91 MM; MFG_NAME01: SAMTEC; MFG_PN01: FTS-105-01-F-D; ROHS: Yes
J18 = HDR-1X4: HDR 1X4 TH 100MIL SP AU 230L; HEIGHT: 5.21 MM; MFG_NAME01: SAMTEC; MFG_PN01: TSW-104-07-T-S; ROHS: Yes
J48 J49 = SMB: CON, SMA, EDGE 0.032IN, 50 OHM FEMALE 18GHZ; ASSY_OPT: DNP; MFG_NAME01: CINCH CONNECTIVITY; MFG_PN01: 142-0701-881; ROHS: Yes
L1 L3 = INDP: IND AIR 5.6NH@100MHZ 300MA 0.3NH 0402; AGILE_PN: 180-76516; CAD_APPROVED: Yes; FPLIST: IND_0402,0402_CC; HEIGHT: 0.55 MM; MFG_NAME01: MURATA; MFG_PN01: LQG15HN5N6S02D; PART_TYPE: INDUCTOR; ROHS: Yes; Tolerance: 0.3NH
L2 L5 = INDUCTOR: IND -- 0.0068UH@100MHZ 300MA 5% 0402; AGILE_PN: 180-30075; CAD_APPROVED: Yes; FPLIST: IND_0402,0402_CC; HEIGHT: 0.55mm; MFG_NAME01: MURATA; MFG_PN01: LQG15HS6N8J02D; ROHS: Yes
L4 = INDUCTOR: IND -- 0.015UH@100MHZ 250MA 5% 0402; FPLIST: IND_0402,0402_CC; HEIGHT: 0.55mm; MFG_NAME01: JOHANSON; MFG_PN01: L-07C15NJV6T; ROHS: Yes
L9 = INDUCTOR: IND -- 0.0047UH@100MHZ 300MA +/-0.3NF 0402; AGILE_PN: 180-30074; CAD_APPROVED: Yes; FPLIST: IND_0402,0402_CC; HEIGHT: 0.55mm; MFG_NAME01: MURATA; MFG_PN01: LQG15HS4N7S02D; ROHS: Yes
L10 L11 = INDUCTOR: IND -- 0.033UH@100MHZ 200MA 5% 0402; AGILE_PN: 180-75099; CAD_APPROVED: YES; FPLIST: IND_0402,0402_CC; HEIGHT: 0.55MM; MFG_NAME01: MURATA; MFG_PN01: LQG15HS33NJ02D; ROHS: Yes; Tolerance: 5%
L12 = INDUCTOR: IND -- 0.002UH@100MHZ 300MA 15% 0402; AGILE_PN: 180-78144; CAD_APPROVED: Yes; FPLIST: IND_0402,0402_CC; HEIGHT: 0.55 MM; MFG_NAME01: MURATA; MFG_PN01: LQG15HS2N0S02; ROHS: Yes
R5 = RES: RES MF 4.7K 1/10W 5% 0603; AGILE_PN: 470-75414; ASSY_OPT: DNP; CAD_APPROVED: Yes; FPLIST: RC0603_OV,RC0603,0603_CC; MFG_NAME01: VISHAY INTERTECHNOLOGY; MFG_PN01: CRCW06034K70JNEA; ROHS: Yes; Tolerance: 5%
R1 R8 R9 = RES: RES MF ZERO OHM 1/10W -- 0603; AGILE_PN: 470-75407; CAD_APPROVED: Yes; FPLIST: RC0603_OV,RC0603,R603-X2,0603_CC; MFG_NAME01: VISHAY INTERTECHNOLOGY; MFG_PN01: CRCW06030000Z0EA; ROHS: Yes; Tolerance: 1%
R10 R11 R17 R18 R28-R30 = RES: RES MF 220 OHM 1/16W 5% 0402; CAD_APPROVED: Yes; FPLIST: RC0402_25,RC0402_HD,0402_CC; MFG_NAME01: VISHAY INTERTECHNOLOGY; MFG_PN01: CRCW0402220RJNED; ROHS: Yes; Tolerance: 5%
R25 R110 = RES: RES MF 10.0K 1/16W 1% AEC-Q200 0402; AGILE_PN: 470-75416; CAD_APPROVED: Yes; FPLIST: RC0402_25,RC0402_HD,0402_CC; HEIGHT: 0.4MM; MFG_NAME01: VISHAY INTERTECHNOLOGY; MFG_PN01: CRCW040210K0FKED; ROHS: Yes; TOL: 1%; Tolerance: 1%
R85 = RES: RES MF 100 OHM 1/16W 5% 0402; CAD_APPROVED: Yes; FPLIST: RC0402_25,RC0402_HD,RC0402_X2,0402_CC; MFG_NAME01: VISHAY INTERTECHNOLOGY; MFG_PN01: CRCW0402100RJNED; ROHS: Yes; Tolerance: 5%
R3 R12 R96 = RES: RES MF ZERO OHM 1/16W 5% 0402; CAD_APPROVED: Yes; FPLIST: RC0402_25,RC0402_HD,RC0402_X2,0402_CC; MFG_NAME01: VISHAY; MFG_PN01: CRCW04020000Z0ED; ROHS: Yes; Tolerance: 5%
R97 R118-R124 R127-R141 = RES: RES MF ZERO OHM 1/16W 5% 0402; ASSY_OPT: DNP; CAD_APPROVED: Yes; FPLIST: RC0402_25,RC0402_HD,RC0402_X2,0402_CC; MFG_NAME01: VISHAY; MFG_PN01: CRCW04020000Z0ED; ROHS: Yes; Tolerance: 5%
R556 = RES: RES MF 10.0K 1/16W 1% AEC-Q200 0402; AGILE_PN: 470-75416; ASSY_OPT: DNP; CAD_APPROVED: Yes; FPLIST: RC0402_25,RC0402_HD,0402_CC; HEIGHT: 0.4MM; MFG_NAME01: VISHAY INTERTECHNOLOGY; MFG_PN01: CRCW040210K0FKED; ROHS: Yes; SIGNAL_MODEL: DEFAULT_RESISTOR_10000OHM_2_1; TOL: 1%; Tolerance: 1%
R557-R559 = RES: RES MF 10.0K 1/16W 1% AEC-Q200 0402; AGILE_PN: 470-75416; CAD_APPROVED: Yes; FPLIST: RC0402_25,RC0402_HD,0402_CC; HEIGHT: 0.4MM; MFG_NAME01: VISHAY INTERTECHNOLOGY; MFG_PN01: CRCW040210K0FKED; ROHS: Yes; SIGNAL_MODEL: DEFAULT_RESISTOR_10000OHM_2_1; TOL: 1%; Tolerance: 1%
S1 = RF_SHIELD_CUSTOM: ASSY_OPT: DNP
SH1 SH3 SH6-SH16 SH40-SH45 = SH_RES: CUT TRACE RESISTOR; FPLIST: RC0402_25_CT,RC0402_HD_CT,0402_CC_CT; MFG_NAME01: NOTACOMPONENT; MFG_PN01: NOTACOMPONENT
SHUNT3 = Shunt: SHUNT 2.54MM 2POS; ASSY_NOTE: J31.1-J31.2; MFG_NAME01: 3M; MFG_PN01: 969102-0000-DA
SHUNT6 = Shunt: SHUNT 2.54MM 2POS; ASSY_NOTE: J41.1-J41.2; MFG_NAME01: 3M; MFG_PN01: 969102-0000-DA
SHUNT7 = Shunt: SHUNT 2.54MM 2POS; ASSY_NOTE: J42.1-J42.2; MFG_NAME01: 3M; MFG_PN01: 969102-0000-DA
SW1-SW5 = SW_TACT-SPST-2_SMD: MFG_Name01: E-SWITCH
TP2 TP4 TP6-TP13 TP17-TP20 TP23 TP24 TP29-TP33 TP35-TP49 TP51 TP104 TP112-TP115 TP119-TP124 = TestLoop: TEST POINT PAD 40MIL DIA SMT, NO PART TO ORDER; AGILE_PN: 211-76643; CAD_APPROVED: Yes; HEIGHT: 0.1MM; MFG_NAME01: NOTACOMPONENT; MFG_PN01: NOTACOMPONENT; ROHS: Yes
U1 = MKW01Z128_LGA_0: IC MCU ARM 48MHZ 128KB FLASH 16KB RAM 1.8-3.6V LGA60; AGILE_PN: TMP-WF-17753; CAD_APPROVED: Yes; HEIGHT: 0.98MM; MFG_NAME01: FREESCALE SEMICONDUCTOR; MFG_PN01: MKW01Z128CHN; PRE_APN: 344-01481; ROHS: Yes
Y1 = XTAL_13Y: XTAL 32MHZ 9PF -- SMT 3.2X2.5MM; AGILE_PN: 230-77690; CAD_APPROVED: Yes; HEIGHT: 0.8MM; MFG_NAME01: NDK; MFG_PN01: EXS00A-CS02368; ROHS: Yes
Y4 = XTAL_SG-30x0LC_0
C26 C49 = CAP_NP: CAP CER 1.0UF 10V 10% X5R 0402; AGILE_PN: 150-75772; CAD_APPROVED: Yes; FPLIST: CC0402_25,CC0402_HD,0402_CC; HEIGHT: 0.6MM; MFG_NAME01: YAGEO AMERICA; MFG_PN01: CC0402KRX5R6BB105; ROHS: Yes; VOLTAGE: 10V
C29 C35 C64 C65 = CAP_NP: CAP CER 4.7UF 6.3V 20% X5R 0402; CAD_APPROVED: Yes; FPLIST: CC0402_25,CC0402_HD,0402_CC; HEIGHT: 0.65MM; MFG_NAME01: MURATA; MFG_PN01: GRM155R60J475ME47D; PRIORITY_PN: 021-00169; ROHS: Yes; SIGNAL_MODEL: DEFAULT_CAPACITOR_4.7e+06pF_2_1; TOL: 10%; Tolerance: 20%; VOLTAGE: 6.3V
C30 C31 = CAP_NP: CAP CER 22PF 50V 5% C0G 0402; AGILE_PN: 150-75266; ASSY_OPT: DNP; CAD_APPROVED: Yes; FPLIST: CC0402_25,CC0402_HD,0402_CC; HEIGHT: 0.635MM; MFG_NAME01: AVX; MFG_PN01: 04025A220JAT2A; ROHS: Yes; Tolerance: 5%; VOLTAGE: 50V
C32 = CAP_NP: CAP CER 2.2UF 10V 10% X7R 0603; AGILE_PN: 150-78564; CAD_APPROVED: Yes; FPLIST: CC0603_OV,CC0603,0603_CC; HEIGHT: 1.25MM; MFG_NAME01: TAIYO YUDEN; MFG_PN01: LMK107B7225KA-T; ROHS: Yes; Tolerance: 10%; VOLTAGE: 10V
C34 = CAP_NP: CAP CER 18PF 50V 5% C0G 0603; AGILE_PN: 150-75116; ASSY_OPT: DNP; CAD_APPROVED: Yes; FPLIST: CC0603_OV,CC0603,0603_CC; HEIGHT: 0.90MM; MFG_NAME01: YAGEO AMERICA; MFG_PN01: CC0603JRNPO9BN180; ROHS: Yes; TOL: 5%; Tolerance: 5%; VOLTAGE: 50V
C60 = CAP_NP: CAP CER 1000PF 50V 5% C0G 0402; AGILE_PN: 150-76334; CAD_APPROVED: Yes; FPLIST: CC0402_25,CC0402_HD,0402_CC; HEIGHT: 0.55MM; MFG_NAME01: MURATA; MFG_PN01: GRM1555C1H102JA01D; ROHS: Yes; Tolerance: 5%; VOLTAGE: 50V
C66 = CAP_NP: CAP CER 0.1UF 16V 10% X7R 0402; AGILE_PN: 150-75182; ASSY_OPT: DNP; CAD_APPROVED: Yes; FPLIST: CC0402_25,CC0402_HD,0402_CC; HEIGHT: 0.635MM; MFG_NAME01: KEMET; MFG_PN01: C0402C104K4RAC; ROHS: Yes; Tolerance: 10%; VOLTAGE: 16V
D4 D5 = LED: LED RED SGL 20MA SMT 0805; CAD_APPROVED: Yes; FPLIST: LED0805,LED2_0805; HEIGHT: 0.9MM; MFG_NAME01: LITE ON; MFG_PN01: LTST-C171KRKT; ROHS: Yes
D11 = LED: LED GRN SGL 20MA 0603; AGILE_PN: 370-76565; CAD_APPROVED: Yes; HEIGHT: 0.67MM; MFG_NAME01: OSRAM; MFG_PN01: LG L29K-G2J1-24-Z; ROHS: Yes
D1-D3 D6 D7 D9 D10 D12 D18 = DIODE_SCHTKY: DIODE SCH 1A 20V MICROSMP SMT; AGILE_PN: 480-76978; CAD_APPROVED: Yes; HEIGHT: 0.73MM; MFG_NAME01: VISHAY INTERTECHNOLOGY; MFG_PN01: MSS1P3L-M3/89A; ROHS: Yes
J8 J9 = CONN_HDR_3X1: HDR 1X3 TH 100MIL SP 339H AU 100L; AGILE_PN: 210-75726; CAD_APPROVED: Yes; HEIGHT: 8.65MM; MFG_NAME01: SAMTEC; MFG_PN01: TSW-103-07-G-S; ROHS: Yes
J15 = USB_MINI_AB_RECEPTACLE: CON 5 USB_MINI_B_RECEPTACLE RA SMT 0.8MM 168H AU; AGILE_PN: 211-79254; CAD_APPROVED: Yes; HEIGHT: 4.27MM; MFG_NAME01: TE CONNECTIVITY; MFG_PN01: 1734035-2; ROHS: Yes
L6 L7 = BEAD: IND FER BEAD 330OHM@100MHZ 2.5A -- SMT; AGILE_PN: 180-30021; CAD_APPROVED: YES; HEIGHT: 1.05 MM; MFG_NAME01: TDK; MFG_PN01: MPZ2012S331A; PART_TYPE: FERRITE; ROHS: Yes; Tolerance: 25%
R13 = RES: RES MF 180K  1/16W 1% 0402; FPLIST: RC0402_25,RC0402_HD,0402_CC; MFG_NAME01: VISHAY; MFG_PN01: CRCW0402180KFKED; ROHS: Yes; SIGNAL_MODEL: DEFAULT_RESISTOR_180000OHM_2_1; Tolerance: 1%
R14 = RES: RES MF ZERO OHM 1/16W 5% 0402; ASSY_OPT: DNP; CAD_APPROVED: Yes; FPLIST: RC0402_25,RC0402_HD,RC0402_X2,0402_CC; HEIGHT: 0.45 MM; MFG_NAME01: VISHAY; MFG_PN01: CRCW04020000Z0ED; PRIORITY_PN: 006-00559; ROHS: Yes; SIGNAL_MODEL: DEFAULT_RESISTOR_0.001OHM_2_1; TOL: 5%; Tolerance: 5%; VOLTAGE: 1/16W
R16 R19-R21 = RES: RES MF 10.0K 1/16W 1% AEC-Q200 0402; AGILE_PN: 470-75416; CAD_APPROVED: Yes; FPLIST: RC0402_25,RC0402_HD,0402_CC; HEIGHT: 0.55MM; MFG_NAME01: VISHAY INTERTECHNOLOGY; MFG_PN01: CRCW040210K0FKED; PRIORITY_PN: 006-00552; ROHS: Yes; SIGNAL_MODEL: DEFAULT_RESISTOR_10000OHM_2_1; TOL: 5%; Tolerance: 1%
R50 R51 = RES: RES MF 33.0 OHM 1/16W 1% 0402; CAD_APPROVED: Yes; FPLIST: RC0402_25,RC0402_HD,RC0402_X2,0402_CC; MFG_NAME01: VISHAY; MFG_PN01: CRCW040233R0FKED; ROHS: Yes; Tolerance: 1%
R52 R116 R117 R125 R126 = RES: RES MF 4.7K 1/10W 5% 0603; CAD_APPROVED: Yes; FPLIST: RC0603_OV,RC0603,0603_CC; MFG_NAME01: VISHAY INTERTECHNOLOGY; MFG_PN01: CRCW06034K70JNEA; ROHS: Yes; Tolerance: 5%
R88-R93 R551 = RES: RES MF 1.0K 1/16W 1% 0402; AGILE_PN: 470-76037; CAD_APPROVED: Yes; FPLIST: RC0402_25,RC0402_HD,RC0402_X2,0402_CC; HEIGHT: 0.4MM; MFG_NAME01: YAGEO AMERICA; MFG_PN01: RC0402FR-071KL; ROHS: Yes; TOL: 1%; Tolerance: 1%
R100 R105 R107 = RES: RES MF 10K 1/10W 5% 0603; AGILE_PN: 470-75410; CAD_APPROVED: Yes; FPLIST: RC0603_OV,RC0603,0603_CC; MFG_NAME01: KOA SPEER; MFG_PN01: RK73B1JTTD103J; ROHS: Yes; Tolerance: 5%
R106 = RES: RES MF 27K 1/16W 5% 0402; AGILE_PN: 470-76069; CAD_APPROVED: Yes; FPLIST: RC0402_25,RC0402_HD,0402_CC; MFG_NAME01: VISHAY INTERTECHNOLOGY; MFG_PN01: CRCW040227K0JNED; ROHS: Yes; Tolerance: 5%
R108 = RES: RES MF 10.0K 1/16W 1% AEC-Q200 0402; AGILE_PN: 470-75416; ASSY_OPT: DNP; CAD_APPROVED: Yes; FPLIST: RC0402_25,RC0402_HD,0402_CC; HEIGHT: 0.4MM; MFG_NAME01: VISHAY INTERTECHNOLOGY; MFG_PN01: CRCW040210K0FKED; ROHS: Yes; TOL: 1%; Tolerance: 1%
R109 = RES: RES MF 15.0K 1/16W 1% 0402; AGILE_PN: 470-76066; CAD_APPROVED: Yes; FPLIST: RC0402_25,RC0402_HD,0402_CC; HEIGHT: 0.4 MM; MFG_NAME01: BOURNS; MFG_PN01: CR0402-FX-1502GLF; ROHS: Yes; TOL: 1%; Tolerance: 1%
R112 = RES: RES MF 27K 1/16W 5% 0402; AGILE_PN: 470-76069; ASSY_OPT: DNP; CAD_APPROVED: Yes; FPLIST: RC0402_25,RC0402_HD,0402_CC; MFG_NAME01: VISHAY INTERTECHNOLOGY; MFG_PN01: CRCW040227K0JNED; ROHS: Yes; Tolerance: 5%
R113 = RES: RES MF 15.0K 1/16W 1% 0402; AGILE_PN: 470-76066; ASSY_OPT: DNP; CAD_APPROVED: Yes; FPLIST: RC0402_25,RC0402_HD,0402_CC; HEIGHT: 0.4 MM; MFG_NAME01: BOURNS; MFG_PN01: CR0402-FX-1502GLF; ROHS: Yes; TOL: 1%; Tolerance: 1%
SHUNT2 = Shunt: SHUNT 2.54MM 2POS; ASSY_NOTE: J9.1-J9.2; MFG_NAME01: 3M; MFG_PN01: 969102-0000-DA
TP3 TP5 TP14 TP15 TP100-TP103 TP107 TP108 TP508-TP512 = TESTLOOP: TEST POINT PAD 30MIL DIA SMT, NO PART TO ORDER; AGILE_PN: 211-76642; CAD_APPROVED: Yes; HEIGHT: 0.1MM; MFG_NAME01: NOTACOMPONENT; MFG_PN01: NOTACOMPONENT; ROHS: Yes
TP105 TP106 = TestLoop: TEST POINT PAD 30MIL DIA SMT, NO PART TO ORDER; AGILE_PN: 211-76642; CAD_APPROVED: Yes; HEIGHT: 0.1MM; MFG_NAME01: NOTACOMPONENT; MFG_PN01: NOTACOMPONENT; ROHS: Yes
U3 U5 = NTSX2102GU8H_8P: IC DUAL SUPPLY XCVR 50 MBPS 5.5V XQFN8; AGILE_PN: 312-80763; CAD_APPROVED: Yes; HEIGHT: 0.5MM; MFG_NAME01: NXP SEMICONDUCTORS; ROHS: Yes; VOLTAGE: 5.5V
U4 = 74-125_14P: IC BUF QUAD TS 1.2-3.6V SSOP14; AGILE_PN: 312-79933; CAD_APPROVED: Yes; HEIGHT: 2mm; MFG_NAME01: NXP SEMICONDUCTORS; ROHS: Yes
U6 = PK20DX128V_QFN_32P: IC MCU FLASH 128KB 50MHZ 1.71-3.6V QFN32; AGILE_PN: 344-01231; CAD_APPROVED: Yes; HEIGHT: 1MM; MFG_NAME01: FREESCALE SEMICONDUCTOR; ROHS: Yes
U7 = MIC2005-0_0.8YM6: IC LIN SW PWR 0.8A 2.5-5.5V SOT23-6; AGILE_PN: 315-79199; CAD_APPROVED: Yes; HEIGHT: 1.45MM; MFG_NAME01: MICREL; ROHS: Yes
U10-U12 = DIODE_TVS_BIDIR: DIODE TVS BIDIR -- 30V 0402; AGILE_PN: 480-76179; CAD_APPROVED: Yes; HEIGHT: 0.44MM; MFG_NAME01: COOPER BUSSMANN; MFG_PN01: 0402ESDA-MLP1; ROHS: Yes
Y3 = CRYSTAL_JXS63: XTAL 8MHZ 20PPM PAR 18PF ESR 200OHM SMT; AGILE_PN: 230-77754; CAD_APPROVED: Yes; HEIGHT: 1.1MM; MFG_NAME01: ABRACON CORP; MFG_PN01: ABM3B-8.000MHZ-B2-T; ROHS: Yes
C6 C38-C40 = CAP_NP: CAP CER 10UF 10V 10% X7R 0805; ASSY_OPT: DNP; CAD_APPROVED: Yes; FPLIST: CC0805_OV,CC0805,0805_CC; HEIGHT: 1.4MM; MFG_NAME01: MURATA; MFG_PN01: GRM21BR71A106KE51L; ROHS: Yes; Tolerance: 10%; VOLTAGE: 10V
C37 C57 = CAP_NP: CAP CER 2.2UF 10V 10% X7R 0603; AGILE_PN: 150-78564; CAD_APPROVED: Yes; FPLIST: CC0603_OV,CC0603,0603_CC; HEIGHT: 1.25MM; MFG_NAME01: TAIYO YUDEN; MFG_PN01: LMK107B7225KA-T; ROHS: Yes; TOL: 10%; Tolerance: 10%; VOLTAGE: 10V
C55 = CAP_NP: CAP CER 1UF 10V 10% X7R 0805; CAD_APPROVED: Yes; FPLIST: CC0805_OV,CC0805,0805_CC; HEIGHT: 1.4MM; MFG_NAME01: MURATA; MFG_PN01: GRM21BR71A105KA01L; ROHS: Yes; Tolerance: 10%; VOLTAGE: 10V
C56 = CAP_NP: CAP CER 470PF 16V 10% X7R 0402; CAD_APPROVED: Yes; FPLIST: CC0402_25,CC0402_HD,0402_CC; HEIGHT: 0.635MM; MFG_NAME01: KEMET; MFG_PN01: C0402C471K4RACTU; ROHS: Yes; Tolerance: 10%; VOLTAGE: 16V
J1 J3 = CONN_2x8_MTCONN
J2 = CONN_2x10_MTCONN
J4 = CONN_2x6_MTCONN
J7 = CONN_HDR_3X1: HDR 1X3 TH 100MIL SP 339H AU 100L; AGILE_PN: 210-75726; ASSY_OPT: DNP; CAD_APPROVED: Yes; HEIGHT: 8.65MM; MFG_NAME01: SAMTEC; MFG_PN01: TSW-103-07-G-S; ROHS: Yes
Q1 = BSS138PS_DUAL: MOSFET - BSS138PS, N-CH, 60V, 0.32A, 1.6 OHM, SC-88; CLASS: IC; Color: Default; Location X-Coordinate: 0; Location Y-Coordinate: 0; MFG_NAME01: NXP; MFG_PN01: BSS138PS,115; Populate: Yes; Power Pins Visible: False; Primitive: DEFAULT; ROHS: YES
R6 = RES: RES MF ZERO OHM 1/10W -- 0603; AGILE_PN: 470-75407; ASSY_OPT: DNP; CAD_APPROVED: Yes; FPLIST: RC0603_OV,RC0603,R603-X2,0603_CC; MFG_NAME01: VISHAY INTERTECHNOLOGY; MFG_PN01: CRCW06030000Z0EA; ROHS: Yes; Tolerance: 1%
SHUNT1 = Shunt: SHUNT 2.54MM 2POS; ASSY_NOTE: J8.2-J8.3; MFG_NAME01: 3M; MFG_PN01: 969102-0000-DA
SHUNT4 = Shunt: SHUNT 2.54MM 2POS; ASSY_NOTE: J43.1-J43.2; MFG_NAME01: 3M; MFG_PN01: 969102-0000-DA
SHUNT5 = Shunt: SHUNT 2.54MM 2POS; ASSY_NOTE: J44.1-J44.2; MFG_NAME01: 3M; MFG_PN01: 969102-0000-DA
TL1 TL2 = TestLoop: TEST POINT PAD SIZE 3.4MM X 1.8MM SMT; AGILE_PN: 211-75906; CAD_APPROVED: Yes; FPLIST: testpoint_135_070mil,testpoint_110_045mil,testpoint_125x40milmod; HEIGHT: 1.53 MM; MFG_NAME01: KEYSTONE ELECTRONICS; MFG_PN01: 5015; ROHS: Yes
TP507 = TestLoop: TEST POINT PC MULTI PURPOSE BLK TH; AGILE_PN: 210-79450; CAD_APPROVED: Yes; HEIGHT: 8.13MM; MFG_NAME01: KEYSTONE ELECTRONICS; MFG_PN01: 5011; ROHS: Yes
U16 U17 = TXB0108
U18 = MIC5205-3V3_SOT23-5

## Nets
5V_USB: D9.A D10.A U7.6(VOUT)
GND: C2.2 C3.2 C4.2 C5.2 C6.2 C9.2 C12.1 C14.2 C15.2 C16.2 C17.2 C18.2 C19.2 C21.2 C22.2 C25.2 C26.2 C27.2 C28.2 C29.2 C30.2 C31.2 C32.2 C33.2 C35.2 C37.2 C38.2 C39.2 C40.2 C41.2 C42.2 C43.2 C44.2 C45.2 C46.2 C48.2 C49.2 C51.2 C52.2 C53.2 C54.2 C55.2 C56.2 C57.2 C59.2 C60.2 C61.2 C62.2 C63.2 C64.2 C65.2 C66.2 C67.2 C68.2 J2.14(B7) J3.12(B6) J3.14(B7) J5.2 J7.2 J13.3(A2) J13.5(A3) J14.3(A2) J14.5(A3) J15.5(P5) J18.1 J28.2 J48.2(SHIELD2) J48.3(SHIELD1) J48.4(SHIELD3) J48.5(SHIELD4) J49.2(SHIELD2) J49.3(SHIELD1) J49.4(SHIELD3) J49.5(SHIELD4) L7.2 R8.2 R10.2 R12.2 R100.2 R109.2 R112.2 S1.1 S1.2 S1.3 S1.4 S1.5 S1.6 S1.7 S1.8 S1.9 S1.10 SH43.1 SW1.2 SW2.2 SW3.2 SW4.2 SW5.2 TL1.1(Pin1) TL2.1(Pin1) TP9.1(Pin1) TP10.1(Pin1) TP11.1(Pin1) TP12.1(Pin1) TP507.1(Pin1) U1.4(VSS1) U1.20(VSS1) U1.36(GND/SCAN) U1.38(GND_PA2) U1.40(GND_PA1) U1.61(FLAG1) U1.62(FLAG2) U3.4(GND) U4.7(GND) U5.4(GND) U6.2(VSS1) U6.8(VSSA) U6.33(EPAD) U7.2(GND) U10.2(A2) U11.2(A2) U12.2(A2) U16.11(GND) U17.11(GND) U18.2(GND) Y1.2 Y1.4 Y3.2(GND1) Y3.4(GND2) Y4.6(GND)
P3V3: C5.1 C37.1 D12.C J46.1 R127.1 R128.2 R138.2 TP7.1(Pin1)
P3V3_BRD: C41.1 C61.1 C63.1 C65.1 D4.A(ANODE) D8.A(ANODE) D17.2(BLUE_C) J45.1 Q1.G1(G2) Q1.G2 R116.1 R117.1 R556.1 R557.1 R558.1 R559.1 TP4.1(Pin1) U5.8(VCCB) U16.2(VCCA) U16.10(OE) U17.2(VCCA) U17.10(OE)
P3V3_LDO: C57.1 D3.A TP2.1(Pin1) U18.5(VOUT)
P5V: D6.C D9.C R139.2 R140.1
P5V0_SDA_USB_CONN_VBUS: J15.1(P1) L6.1 U10.1(A1)
P5V_SDA: C33.1 C34.1 C49.1 D18.C R52.1 R108.1 TP104.1(Pin1) U6.6(VREGIN) U7.1(VIN)
VSSA: C36.2 R8.1 U1.3(VSSA)
A1/INT: J4.4(B2) R137.2
A2/INT: J4.6(B3) R135.2
A3/INT: J4.8(B4) R134.2
A4/SDA/INT: J4.10(B5) R133.2
A5/SCL/INT: J4.12(B6) R132.2
D0/RX/INT: J1.2(B1) U17.12(B8)
D1/TX/INT: J1.4(B2) U17.13(B7)
D2/INT: J1.6(B3) U17.14(B6)
D3/PWM/INT: J1.8(B4) U17.15(B5)
D4/INT: J1.10(B5) U17.16(B4)
D5/PWM/INT: J1.12(B6) U17.17(B3)
D6/PWM/INT: J1.14(B7) U17.18(B2)
D7/CMP/INT: J1.16(B8) U17.20(B1)
D8/Int: J2.2(B1) U16.12(B8)
D9/Int: J2.4(B2) U16.13(B7)
D10/SPI_SS: J2.6(B3) U16.14(B6)
D11/MOSI: J2.8(B4) U16.15(B5)
D12/MISO: J2.10(B5) U16.16(B4)
D13/SCK: J2.12(B6) U16.17(B3)
DIO0: R122.1 SH40.1 TP49.1(Pin1) U1.49(DIO0/PTE2)
DIO1: J18.2 R123.1 SH41.1 TP47.1(Pin1) U1.50(DIO1/PTE3)
DIO2: J18.3 R129.1 TP45.1(Pin1) U1.51(DIO2)
DIO3: R130.1 TP44.1(Pin1) U1.52(DIO3)
DIO4: J10.1 R131.1 TP43.1(Pin1) U1.53(DIO4)
DIO5/CLKOUT: SH45.1 TP42.1(Pin1) U1.54(DIO5/CLKOUT)
EXTAL_32M: C20.1 C21.1 U1.46(XTA) Y1.1
IO_REF: C48.1 C62.1 C64.1 J3.4(B2) R20.2 R21.1 R125.1 R126.1 R138.1 R139.1 TP124.1(Pin1) U5.1(VCCA) U16.19(VCCB) U17.19(VCCB)
P5-9V_VIN: C6.1 C38.1 C39.1 D1.A J3.16(B8) J7.1
PA_BOOST: L12.1 U1.41(PA_BOOST)
PA_BOOST_EXT: C1.1 C2.1 C47.1 L1.2
POWER_EN: R551.1 U6.31(ADC0_SE7B/PTD6/SPI0_PCS3/UART0_RX/FTM0_CH6/FTM0_FLT0/LLWU_P15)
PTA0/SWD_CLK: J35.1 SH1.2 TP36.1(Pin1) U1.10(PTA0/SWD_CLK)
PTA1/UART0_RX: J41.2 R89.2 SH15.2 TP113.1(Pin1)
PTA2/UART0_TX: J42.1 R88.2 SH16.2 TP114.1(Pin1)
PTA3/SWD_DIO: J14.2(B1) R25.1 R92.2 SH7.2 TP32.1(Pin1) U1.11(PTA3/SWD_DIO)
PTA4/NMI: C53.1 R133.1 R558.2 SW4.1 TP29.1(Pin1) U1.12(PTA4/NMI_b)
PTA18: SH45.2 U1.15(PTA18/EXTAL0)
PTA19: J10.2 R136.1 TP115.1(Pin1) U1.16(PTA19/XTAL0)
PTB0: R29.2 R132.1 TP120.1(Pin1) U1.17(PTB0)
PTB1: J18.4 R28.2 SH11.2 TP121.1(Pin1) U1.18(PTB1)
PTB2: R91.2 SH12.2 TP123.1(Pin1) U1.21(PTB2)
PTB17: R90.2 SH14.2 TP122.1(Pin1) U1.22(PTB17)
PTC1: R97.2 SH10.2 TP112.1(Pin1)
PTC1/RTC_IN: R96.1 R97.1 U1.24(PTC1/ADC0_SE15)
PTC2: C52.1 R557.2 SH9.2 SW3.1 TP24.1(Pin1) U1.25(PTC2/ADC0_SE11)
PTC3: SH40.2 U1.26(PTC3)
PTC4: SH41.2 U1.23(PTC4/DISABLED)
PTD4/SPI1_PCS0: SH3.2 U1.27(PTD4)
PTD5/SPI1_SCK: SH6.2 U1.28(PTD5)
PTD6/LLWU_P15: C51.1 R134.1 R556.2 SW1.1 TP23.1(Pin1) U1.29(PTD6)
PTD7: C54.1 R559.2 SH8.2 SW2.1 TP30.1(Pin1) U1.31(PTD7)
PTE0/SPI1_MISO: J44.1 U1.32(PTE0/DISABLED)
PTE1/SPI1_MOSI: J43.2 U1.34(PTE1)
PTE16: R11.2 R137.1 TP119.1(Pin1) U1.5(PTE16/ADC0DP1/ADC0_SE1)
PTE17: R30.2 R135.1 U1.6(PTE17/ADC0_DM1/ADC0_SE5a)
PTE18/I2C0_SDA: Q1.S2 R117.2 R119.1 U1.7(PTE18/ADC0_DP2/ADC0_SE2)
PTE19/I2C0_SCL: Q1.S1(S2) R116.2 R118.1 U1.8(PTE19/ADC0_DM2/ADC0_SE6a)
PTE30: R85.1 U1.9(PTE30/DAC_OUT/ADC0_SE23/CMP0_IN4)
RESET_B_TGTMCU: J11.2 U6.21(ADC0_SE9/TSI0_CH6/PTB1/I2C0_SDA/FTM1_CH1/FTM1_QD_PHB)
RESET_B_XCVR: J31.1 R5.1 U1.48(RESET)
RESET_TGTMCU_B: D5.C(CATHODE) J9.3 J14.10(B5) R13.2 R14.2 R124.1 TP35.1(Pin1) U1.33(PTA20/RESET_b) U3.7(B1) U5.7(B1)
RFIO: L9.1 U1.39(RFIO)
RFIO_EXT: C4.1 C7.1 C50.1 C58.1 L2.2
RXTX: R141.1 TP37.1(Pin1) U1.37(RXTX)
SDA_EXTAL: C31.1 U6.17(EXTAL0/PTA18/FTM0_FLT2/FTM_CLKIN0) Y3.3
SDA_JTAG_TCLK: J13.4(B2) TP509.1(Pin1) U6.12(JTAG_TCLK/SWD_CLK/EZP_CLK/TSI0_CH1/PTA0/~{UART0_CTS}/~{UART0_COL}/FTM0_CH5)
SDA_JTAG_TDI: J13.8(B4) TP511.1(Pin1) U6.13(JTAG_TDI/EZP_DI/TSI0_CH2/PTA1/UART0_RX/FTM0_CH6)
SDA_JTAG_TDO: J13.6(B3) TP510.1(Pin1) U6.14(JTAG_TDO/TRACE_SWO/EZP_DO/TSI0_CH3/PTA2/UART0_TX/FTM0_CH7)
SDA_JTAG_TMS: J13.2(B1) R107.2 TP508.1(Pin1) U6.15(JTAG_TMS/SWD_DIO/TSI0_CH4/PTA3/~{UART0_RTS}/FTM0_CH0)
SDA_LED: D11.C(CATHODE) TP106.1(Pin1) U6.29(PTD4/SPI0_PCS1/~{UART0_RTS}/FTM0_CH4/EWM_IN/LLWU_P14)
SDA_RST: J13.10(B5) R52.2 R100.1 TP105.1(Pin1) TP512.1(Pin1) U6.19(~{RESET})
SDA_RST_TGTMCU_J_B: J9.1 J11.1 R14.1 R16.2 U3.2(A1)
SDA_SPI0_SCK: U4.12(4A) U6.26(PTC5/SPI0_SCK/LPTMR0_ALT2/I2S0_RXD0/CMP0_OUT/LLWU_P9)
SDA_SPI0_SIN: R112.1 U4.8(3Y) U6.28(CMP0_IN1/PTC7/SPI0_SIN/USB_SOF_OUT/I2S0_RX_FS)
SDA_SPI0_SOUT: U4.2(1A) U6.27(CMP0_IN0/PTC6/SPI0_SOUT/PDB0_EXTRG/I2S0_RX_BCLK/I2S0_MCLK/LLWU_P10)
SDA_SWD_EN: R106.2 U4.10(~{OE3}) U4.13(~{OE4}) U6.16(~{NMI}/~{EZP_CS}/TSI0_CH5/PTA4/FTM0_CH1/LLWU_P3)
SDA_SWD_OE_B: R105.1 U4.1(~{OE1}) U6.20(ADC0_SE8/TSI0_CH0/PTB0/I2C0_SCL/FTM1_CH0/FTM1_QD_PHA/LLWU_P5)
SDA_USB_CONN_DN: J15.2(P2) R50.1 U12.1(A1)
SDA_USB_CONN_DP: J15.3(P3) R51.1 U11.1(A1)
SDA_USB_DN: R50.2 U6.4(USB0_DM)
SDA_USB_DP: R51.2 U6.3(USB0_DP)
SDA_USB_VOUT33: C26.1 C29.1 C32.1 C66.1 D7.A J13.1(A1) R16.1 R17.1 R19.2 R105.2 R106.1 R107.1 R110.1 TP103.1(Pin1) U3.1(VCCA) U4.4(~{OE2}) U4.14(VCC) U6.1(VDD1) U6.5(VOUT33) U6.7(VDDA) U6.11(VBAT)
SDA_USBSHIELD: J15.S1(SHLD1) J15.S2(SHLD2) J15.S3(SHLD3) J15.S4(SHLD4) L7.1
SDA_XTAL: C30.1 U6.18(XTAL0/PTA19/FTM1_FLT0/FTM_CLKIN1/LPTMR0_ALT1) Y3.1
SW1_RST_B: C60.1 J9.2 R113.2 SW5.1
SWD_CLK_TGTMCU: J14.4(B2) J35.2 R93.2 TP51.1(Pin1)
SWD_CLK_TGTMCU_R: R93.1 U4.11(4Y)
SWD_DIO_TGTMCU: R92.1 U4.3(1Y) U4.9(3A)
TC_EXTAL_TP: TP102.1(Pin1) U6.10(EXTAL32)
TC_SDA_USB_ID_TP: J15.4(P4) TP100.1(Pin1)
TC_XTAL_TP: TP101.1(Pin1) U6.9(XTAL32)
UART1_CTS_TGTMCU: R90.1 U6.22(ADC0_SE15/TSI0_CH14/PTC1/SPI0_PCS3/~{UART1_RTS}/FTM0_CH0/I2S0_TXD0/LLWU_P6)
UART1_RST_TGTMCU: R91.1 U6.23(ADC0_SE4B/CMP1_IN0/TSI0_CH15/PTC2/SPI0_PCS2/~{UART1_CTS}/FTM0_CH1/I2S0_TX_FS)
UART1_RX_TGTMCU: R89.1 U6.25(PTC4/SPI0_PCS0/UART1_TX/FTM0_CH3/CMP1_OUT/LLWU_P8)
UART1_TX_TGTMCU: R88.1 U6.24(CMP1_IN1/PTC3/SPI0_PCS1/UART1_RX/FTM0_CH2/I2S0_TX_BCLK/LLWU_P7)
V_EXT: D2.A J28.1
V_MCU: C27.1 C35.1 C42.1 C43.1 C59.1 J14.1(A1) J40.1 R5.2 R9.2 R13.1 R18.2 R25.2 R113.1 SH42.1 TP6.1(Pin1) U1.19(VDD) U1.55(VDD) U3.8(VCCB) Y4.1(VIO) Y4.12(VCC)
V_RF: C19.1 C25.1 J47.1 TP13.1(Pin1) U1.35(VBAT2) U1.43(VBAT1)
VR_ANA: C44.1 TP46.1(Pin1) U1.44(VR_ANA)
VR_DIG: C28.1 TP48.1(Pin1) U1.45(VR_DIG)
VR_PA: C14.1 C16.1 C17.1 C18.1 L10.1 L11.1 U1.42(VR_PA)
VTRG_EN: R108.2 R109.1 R551.2 U7.3(ENABLE)
VTRG_FAULT_B: R110.2 U6.32(PTD7/CMT_IRO/UART0_TX/FTM0_CH7/FTM0_FLT1) U7.4(~{FAULT})
XCVR-SPI_CLK: TP38.1(Pin1) U1.59(SCK/PTC5)
XCVR-SPI_MISO: TP39.1(Pin1) U1.57(MISO/PTC7)
XCVR-SPI_MOSI: TP41.1(Pin1) U1.60(MOSI/PTC6)
XCVR-SPI_SS_B: TP40.1(Pin1) U1.58(NSS/PTD0)
XTAL_32M: SH44.1 U1.47(XTB)
N23353475: C20.2 J5.1
N23353504: C22.1 SH44.2 Y1.3
N23486779: TP108.1(Pin1) U4.6(2Y)
N23497733: C34.2 U7.5(CSLEW)
N23735993: J3.10(B5) R140.2
N23736069: J3.6(B3) SH13.1
N23818123: C40.1 D6.A J7.3
N23859389: J1.3(A2) R122.2
N23859394: J1.5(A3) R123.2
N23859399: J1.7(A4) R129.2
N23868552: J42.2 U1.13(PTA2/DISABLED)
N23868554: J41.1 U1.14(PTA1/DISABLED)
N23869363: C36.1 R9.1 U1.56(VDDA)
N23870337: C13.1 C15.1 L9.2 L11.2
N23870339: C11.2 C13.2 C46.1 L5.1
N23870349: C7.2 C9.1 C11.1 L2.1 L5.2
N23870369: C1.2 C3.1 C8.1 L1.1 L3.2
N23870499: C10.1 C12.2 L10.2 L12.2
N23870540: C8.2 C10.2 C45.1 L3.1
N23886926: J1.9(A5) R130.2
N23887030: J1.11(A6) R131.2
N23913269: J31.2 R85.2
N23918308: D18.A L6.2
N23923482: J4.2(B1) R136.2
N23926816: TP3.1(Pin1) U3.3(A2)
N23926819: TP5.1(Pin1) U3.6(B2)
N23926865: R19.1 U3.5(OE)
N23927016: D5.A(ANODE) R18.1
N23933963: R12.1 TP107.1(Pin1) U4.5(2A)
N23941230: J2.18(B9) Q1.D2 R121.2 R126.2
N23941233: J2.20(B10) Q1.D1(D2) R120.2 R125.2
N23941622: SH6.1 U16.4(A3)
N23941631: SH3.1 U16.7(A6)
N23941634: SH7.1 U16.8(A7)
N23941637: SH1.1 U16.9(A8)
N23943103: SH8.1 U17.1(A1)
N23943106: SH9.1 U17.3(A2)
N23943109: SH10.1 U17.4(A3)
N23943112: SH11.1 U17.5(A4)
N23943115: SH12.1 U17.6(A5)
N23943118: SH14.1 U17.7(A6)
N23943121: SH15.1 U17.8(A7)
N23943124: SH16.1 U17.9(A8)
N23943348: R120.1 U16.20(B1)
N23943351: R121.1 U16.18(B2)
N23958500: R118.2 U16.1(A1)
N23958507: R119.2 U16.3(A2)
N23972508: C47.2 J48.1(CENTER)
N23972666: C58.2 J49.1(CENTER)
N23977839: C55.1 D1.C D10.C J8.3 R3.1 U18.1(VIN)
N23977884: D2.C J8.2 TP33.1(Pin1)
N23977917: D3.C J40.2 J45.2 J46.2 J47.2 R1.2 R6.2 TP31.1(Pin1)
N23977919: J8.1 R1.1
N23978170: D7.C R6.1
N23978250: D4.C(CATHODE) R10.1 TP8.1(Pin1)
N23978332: R3.2 U18.3(ON/~{OFF})
N23978342: C56.1 U18.4(BYP)
N23993054: D17.1(RED) R11.1 TP18.1(Pin1)
N23993056: D17.4(GREEN) R28.1 TP19.1(Pin1)
N23993058: D17.3(BLUE) R29.1 TP20.1(Pin1)
N24008143: J2.16(B8) R128.1
N24082518: R96.2 Y4.7(OUT)
N24091032: C50.2 C67.1 L4.1
N24091265: ANT1.2(Feed) C68.1 L4.2
N24125287: SH42.2 U1.1(VREFH)
N24125299: SH43.2 U1.2(VREFL)
N24162373: TP15.1(Pin1) U5.6(B2)
N24162382: R20.1 U5.5(OE)
N24162397: R21.2 R124.2 SH13.2 U5.2(A1)
N24165182: D12.A J3.8(B4) R127.2
N24184722: J44.2 U16.5(A4)
N24184751: J43.1 U16.6(A5)
N24192363: D11.A(ANODE) R17.2
N24196405: D8.C(CATHODE) R30.1 TP17.1(Pin1)
N24197507: TP14.1(Pin1) U5.3(A2)
N24206241: J1.1(A1) R141.2

Not connected (* = marked no-connect by the designer): J1 13(A7)* 15(A8)*; J2 1(A1)* 3(A2)* 5(A3)* 7(A4)* 9(A5)* 11(A6)* 13(A7)* 15(A8)* 17(A9)* 19(A10)*; J3 1(A1)* 2(B1)* 3(A2)* 5(A3)* 7(A4)* 9(A5)* 11(A6)* 13(A7)* 15(A8)*; J4 1(A1)* 3(A2)* 5(A3)* 7(A4)* 9(A5)* 11(A6)*; J13 7(A4)* 9(A5)*; J14 6(B3)* 7(A4)* 8(B4)* 9(A5)*; U1 30(NC)*; U6 30(ADC0_SE6B/PTD5/SPI0_PCS2/~{UART0_CTS}/~{UART0_COL}/FTM0_CH5/~{EWM_OUT})*; Y4 2(NC2)* 3(NC3)* 4(NC4)* 5(NC5)* 8(NC8)* 9(NC9)* 10(NC10)* 11(NC11)*

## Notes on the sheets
sheet 1
- Table of Contents
- Revisions
- 2
- NOTES
- Rev
- Description
- Date
- Approved
- 3
- Block Diagram
- A
- Initial Release
- AQ
- 8/11/2015
- 4
- MICROCONTROLLER
- A1
- Update antenna match
- 1/20/2016
- AQ
- 5
- FRDM CONNECTORS and POWER
- 6
- OpenSDA
- FRDM-KW019032
- SCH-28745
sheet 2
- TODO: UPDATE REFDES and NOTES
  1. Unless Otherwise Specified:
- All resistors are in ohms, 5%, 1/8 Watt
- All capacitors are in uF, 20%, 50V
- All voltages are DC
- All polarized capacitors are aluminum electrolytic
- 2. Interrupted lines coded with the same letter or letter
      combinations are electrically connected.
- 3. Device type number is for reference only. The number
      varies with the manufacturer.
- 4. Special signal usage:
- _B Denotes - Active-Low Signal
- <> or [] Denotes - Vectored Signals
- 5. Interpret diagram in accordance with American
  National Standards Institute specifications, current
  revision, with the exception of logic block symbology.
- 6. Using this board as an Arduino Host may require populating
  one or more of the following bottom side resistors:
    -To source 3.3V to J3.10: populate R127
    -To source 5V to J3.12: populate R140
    -To source J3.6 and  IO_REF: populate R139 (5V) or R138 (3.3V)
    -To source 3.3V to J2.16: populate R128
- SCH-28745
sheet 3
- SCH-28745
sheet 4
- MKW01 MCU
- CAD Note:
  TX/RX POKA-YOKE:
  Place both jumpers
  with the same orientation
  right next to each other.
- SWD_CLK
- RX
- TX
- SWD_DIO
- CAD Note: Place TP42 close
  to processor pin
- Capacitors
  share pin 1
- LEDs
- XTAL_32M
- XTAL_32K
- Top side cut trace
  Cut when using external
  source on J5
- R96 and R97
  share pin 1
- PUSH BUTTONS
- EMI SHIELD
  PATTERN
- Header shorted with trace on bottom layer.
  Cut trace to isolate the on-board MCU from
  the OpenSDA debug interface
- BER TEST CONNECTOR
- JTAG / SWD
- PIN FUNCTIONS
          USED
- DCLK
- DATA
- SWD_CLK
- PTA20
- SCH-28745
sheet 5
- FRDM / ARDUINO HEADERS
         & LEVEL SHIFTERS
- Populate for I2C0 (Default)
  DNP for GPIO
- I2C0
- R118 & R119:
  DNP for I2C0 (Default)
  Populate for GPIO
- CAD Note:
  TX/RX POKA-YOKE:
- R120 & R121:
  DNP for I2C0 (Default)
  Populate for GPIO
- SPI1
- UART0
- 5VDC VR
  SUPPORT
- Using this board as an Arduino Host may require populating
  one or more of the following bottom side resistors:
  To source 3.3V to J3.10: populate R127
  To source 5V to J3.12: populate R140
  To source J3.6 and  IO_REF: populate R139 (5V) or R138 (3.3V)
  To source 3.3V to J2.16: populate R128
- IN
- OUT
- 5V
- (1.65V - 5.5V)
- Headers are shorted by a cut-trace
  on bottom layer.  Trace may be cut
  to make current measurements.
- POWER MANAGEMENT
- OpenSDA
  K20 3.3V LDO
- LED VOLTAGE  / Peripherals
- For External Power Supply:
  3.6V - 15V shunt J8 2-3 (Default)
  1.8V - 3.6V shunt J8 1-2
- POWER ON
       LED
- External Supply Voltage
            15V Max
- MCU VOLTAGE
- 15Vmax
- FRDM/Arduino Connector
                5V - 9V
- RF VOLTAGE
- ARDUINO J3
- USB 5V (OpenSDA)
- SCH-28745
sheet 6
- RESET
- 1-2: Default.
  2-3: Reset signal direct
  to the MCU, to use when
  OpenSDA is not powered.
- RST Push Button
  Bypass
- DEBUGGER
- Output to system
  from Level shifter
- TARGET MCU
  INTERFACE
  SIGNALS
- TX
- RX
- CTS
- RTS
- PU/PD LOGIC:
  SERIAL INTERFACE
  IS ALWAYS RESET
  WHEN USB PORT
  IS DISCONNECTED
- OpenSDA INTERFACE
- SPARE 74HC125 buffer
- OpenSDA INTERFACE JTAG CONNECTOR
- SCH-28745
